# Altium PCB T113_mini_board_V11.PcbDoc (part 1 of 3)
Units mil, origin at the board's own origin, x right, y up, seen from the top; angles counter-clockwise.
Board outline 2716.54 x 2716.54 mil, 4 copper layers (Top Layer, GND, PWR, Bottom Layer); 97 components, 127 nets, 497 pads, 287 vias.
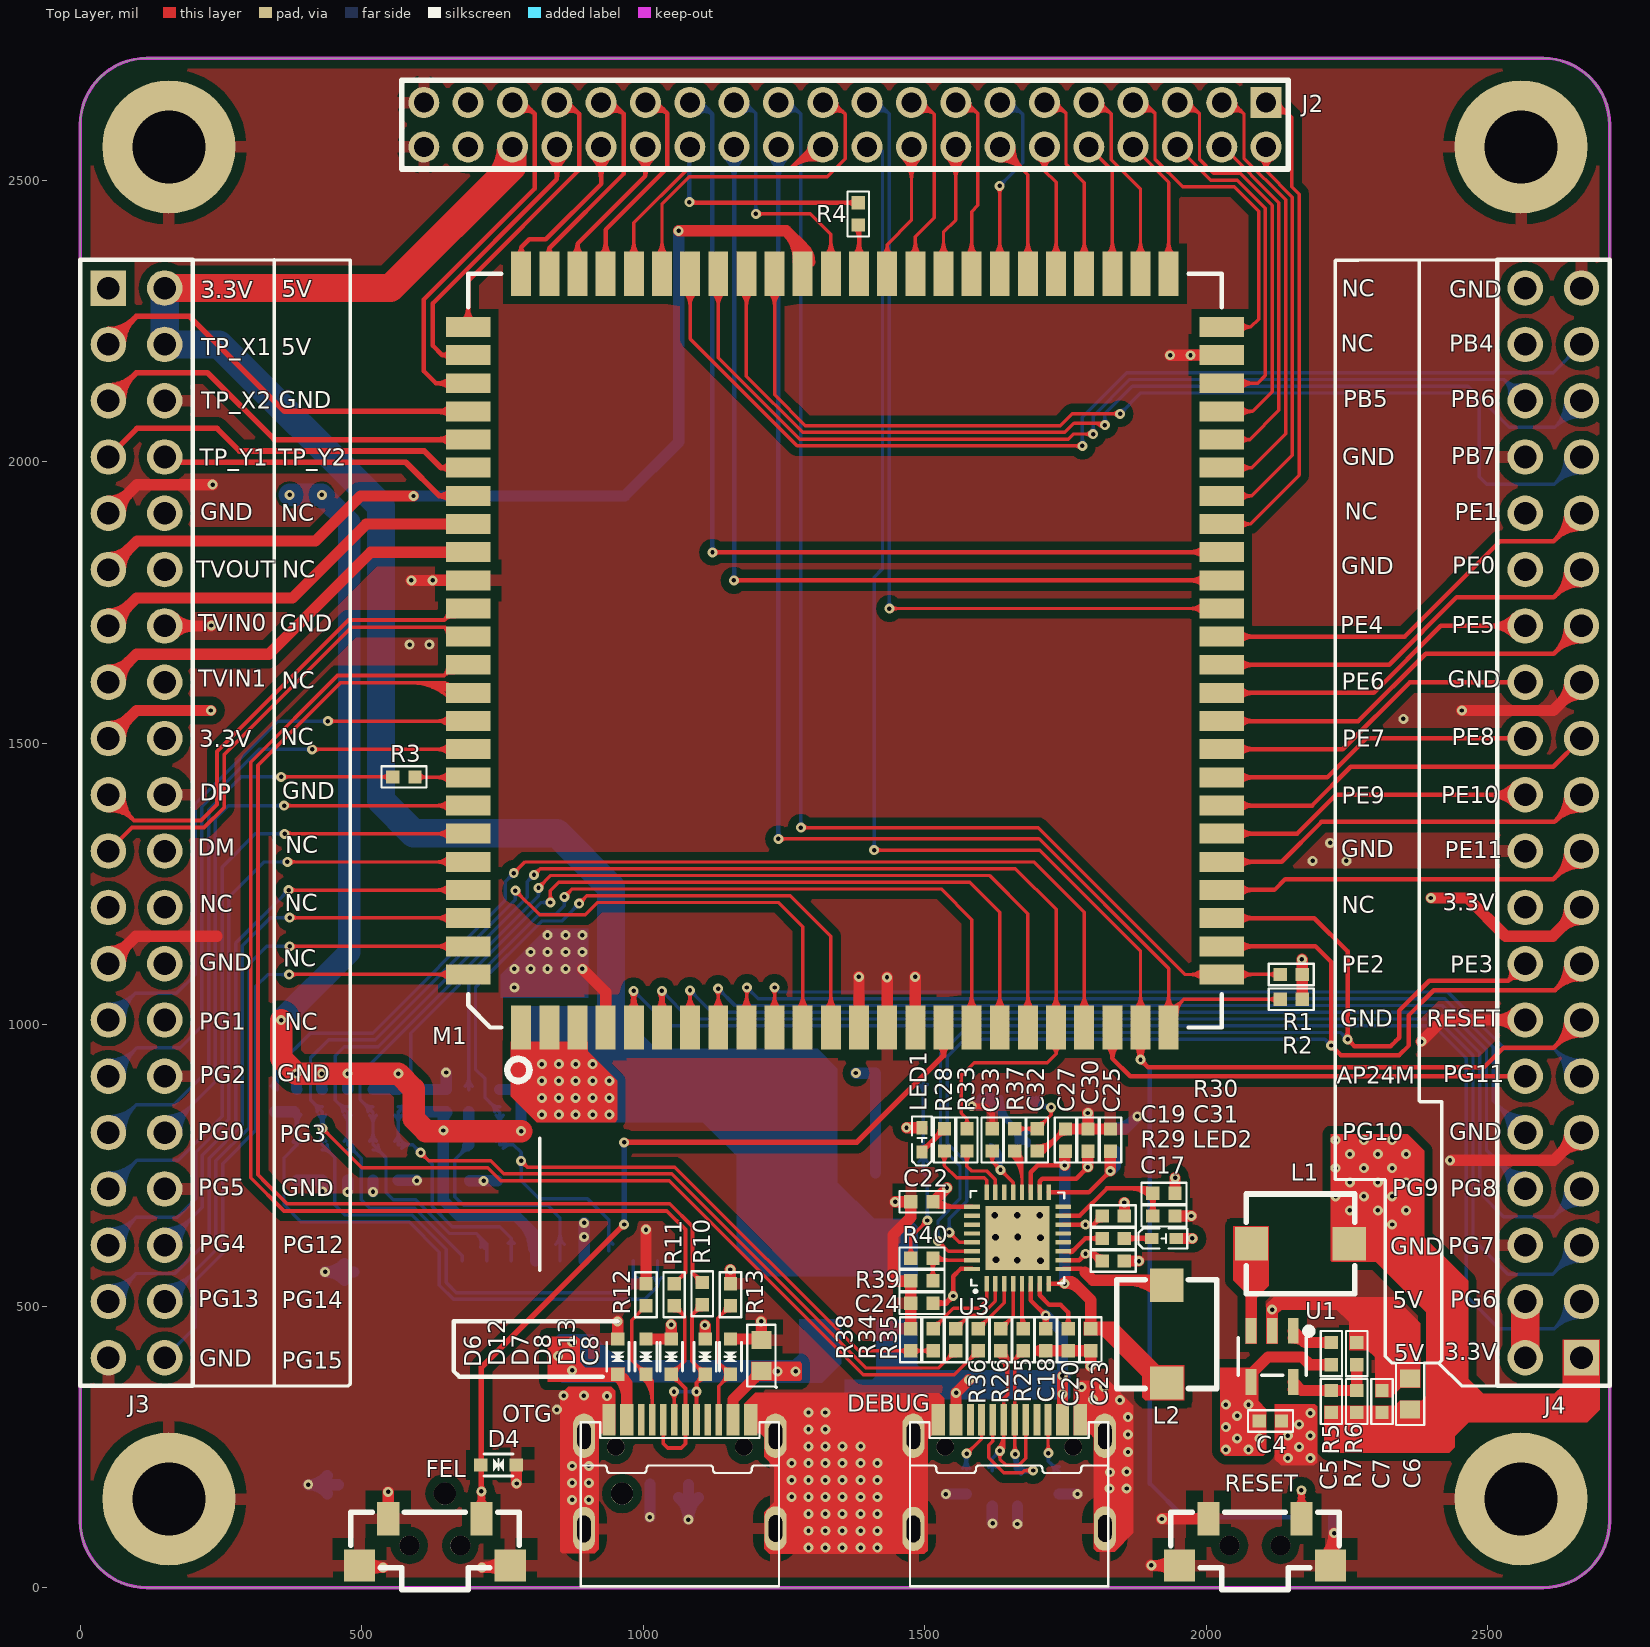
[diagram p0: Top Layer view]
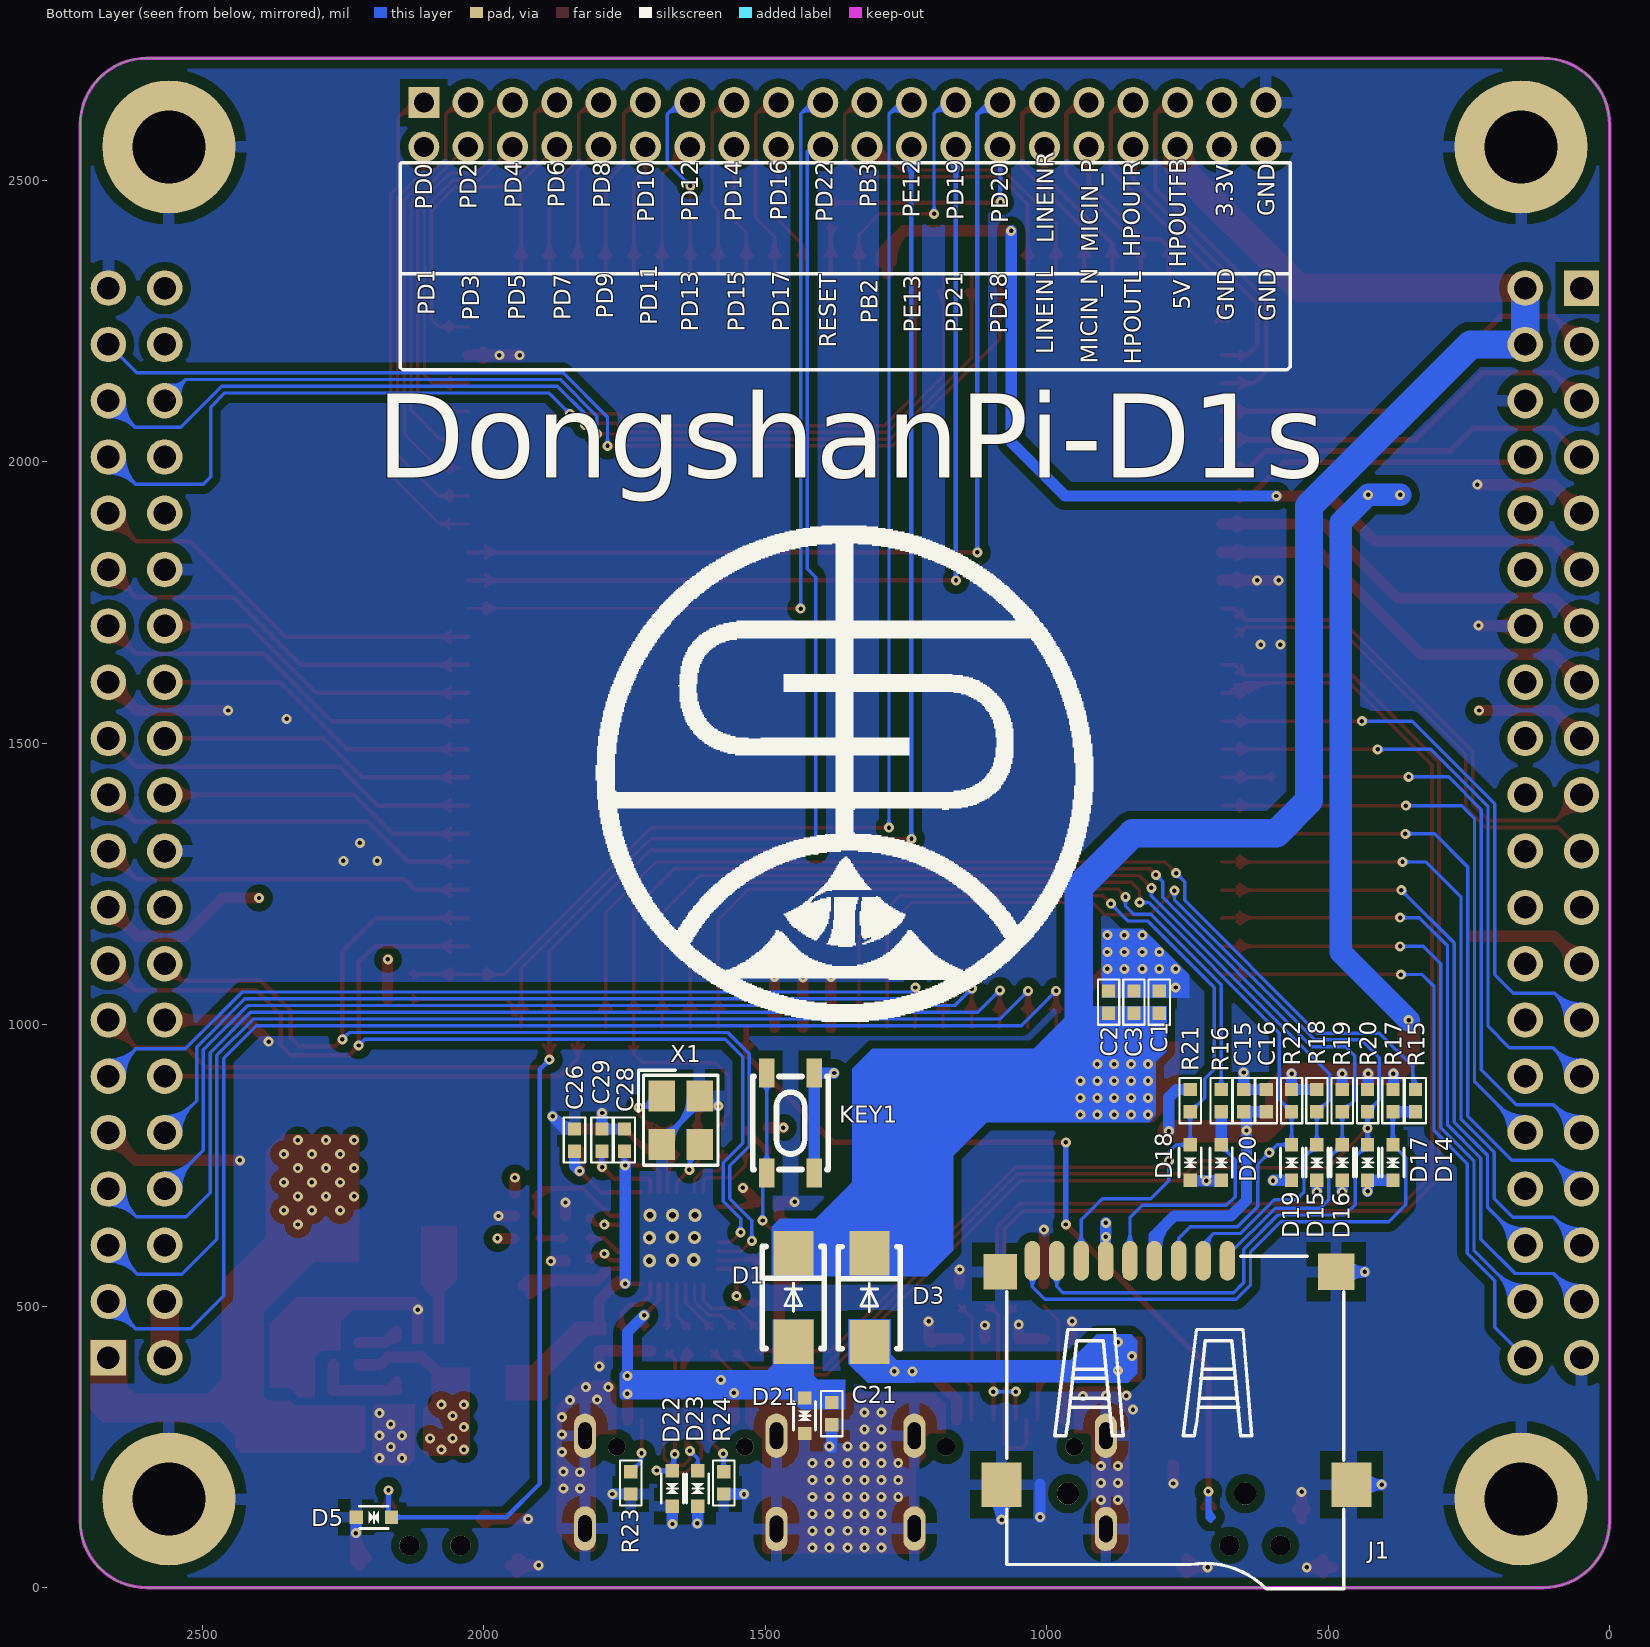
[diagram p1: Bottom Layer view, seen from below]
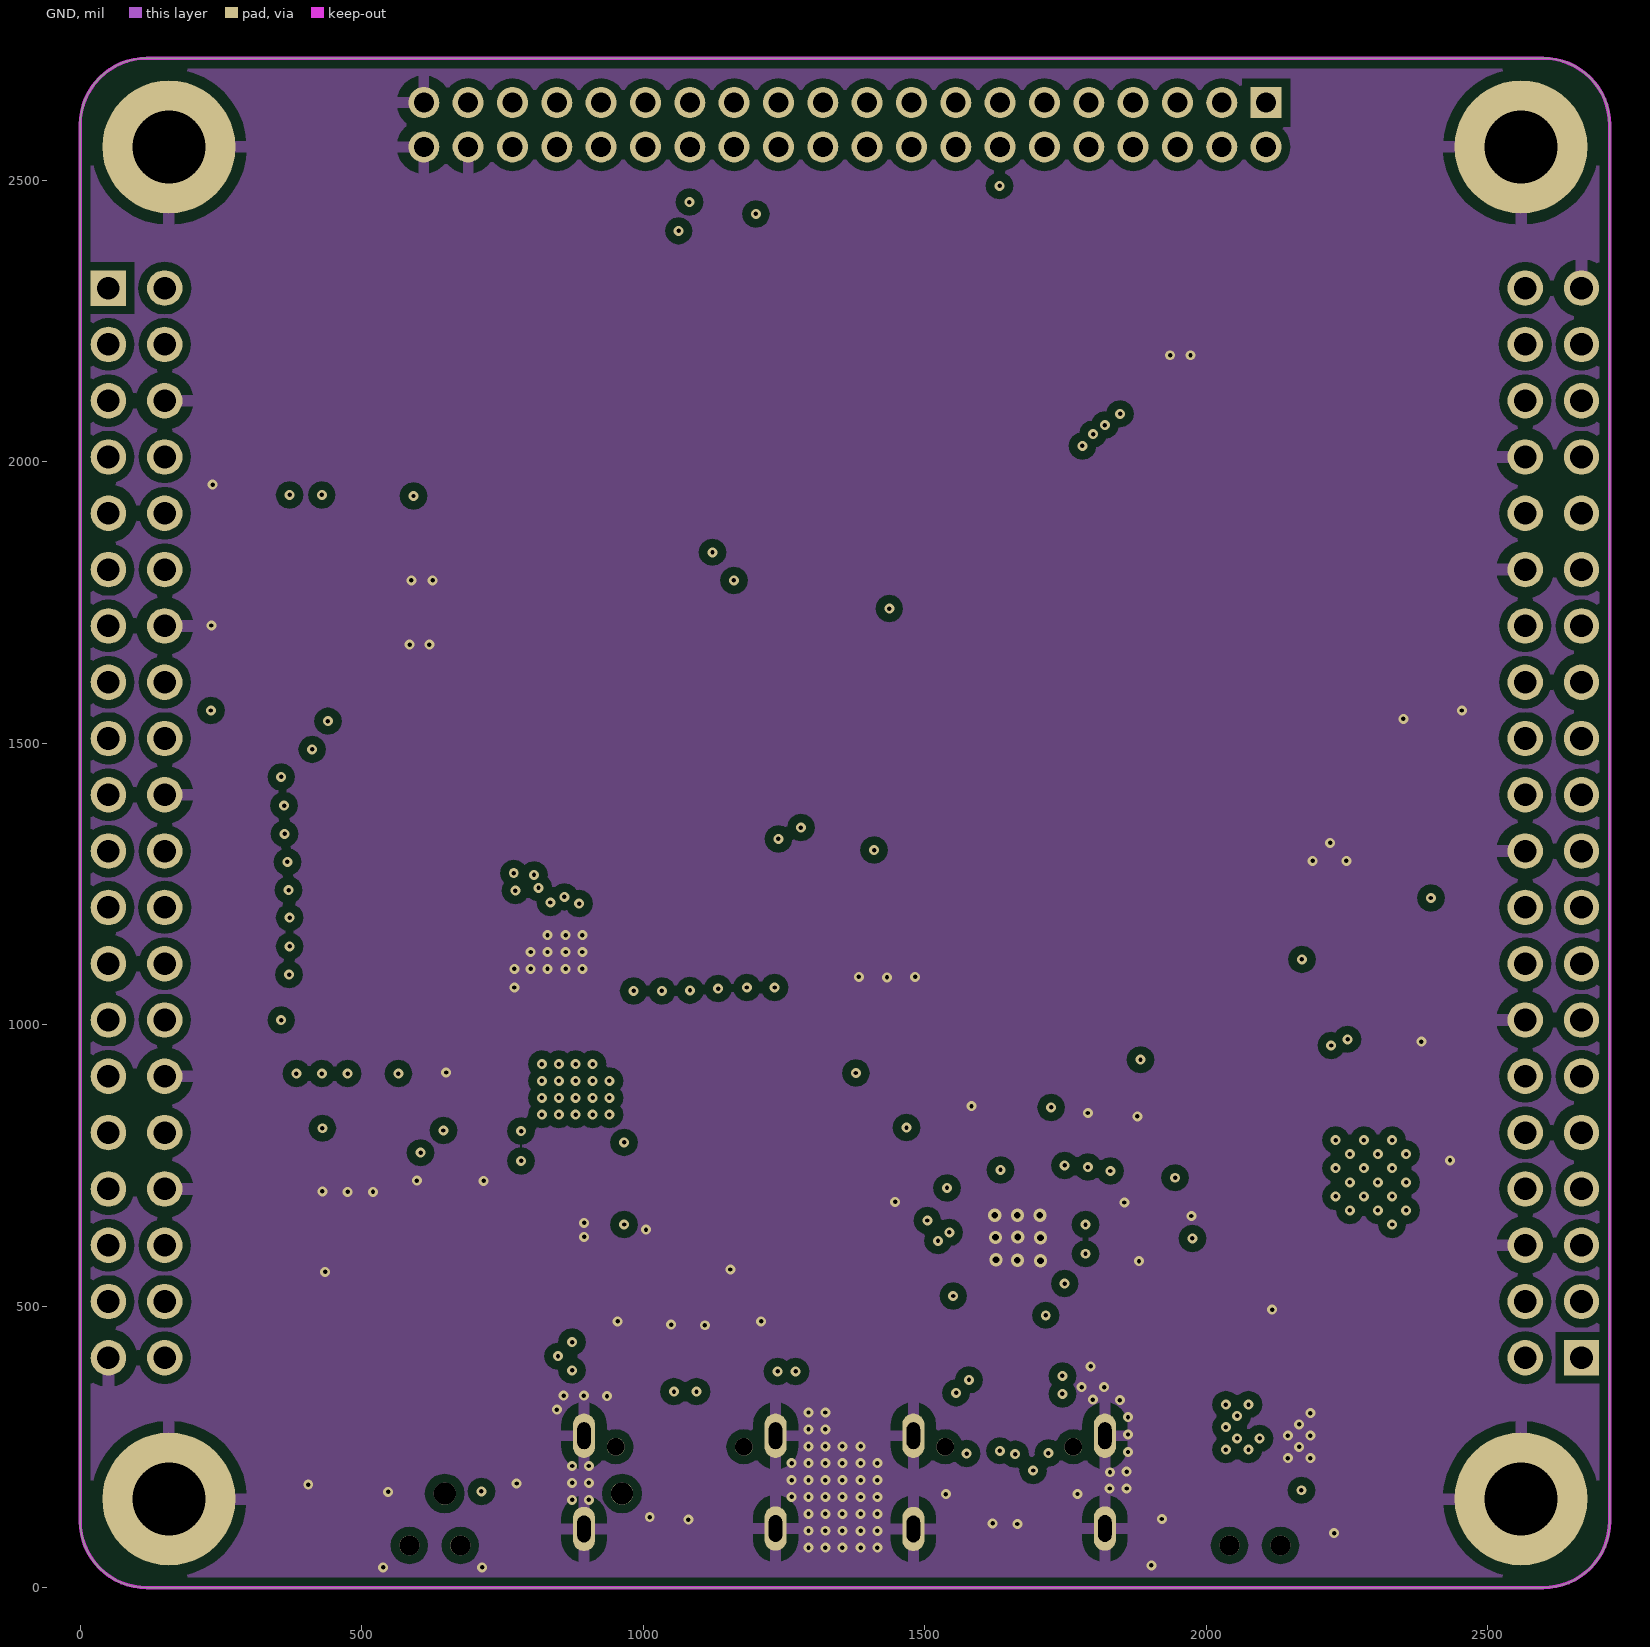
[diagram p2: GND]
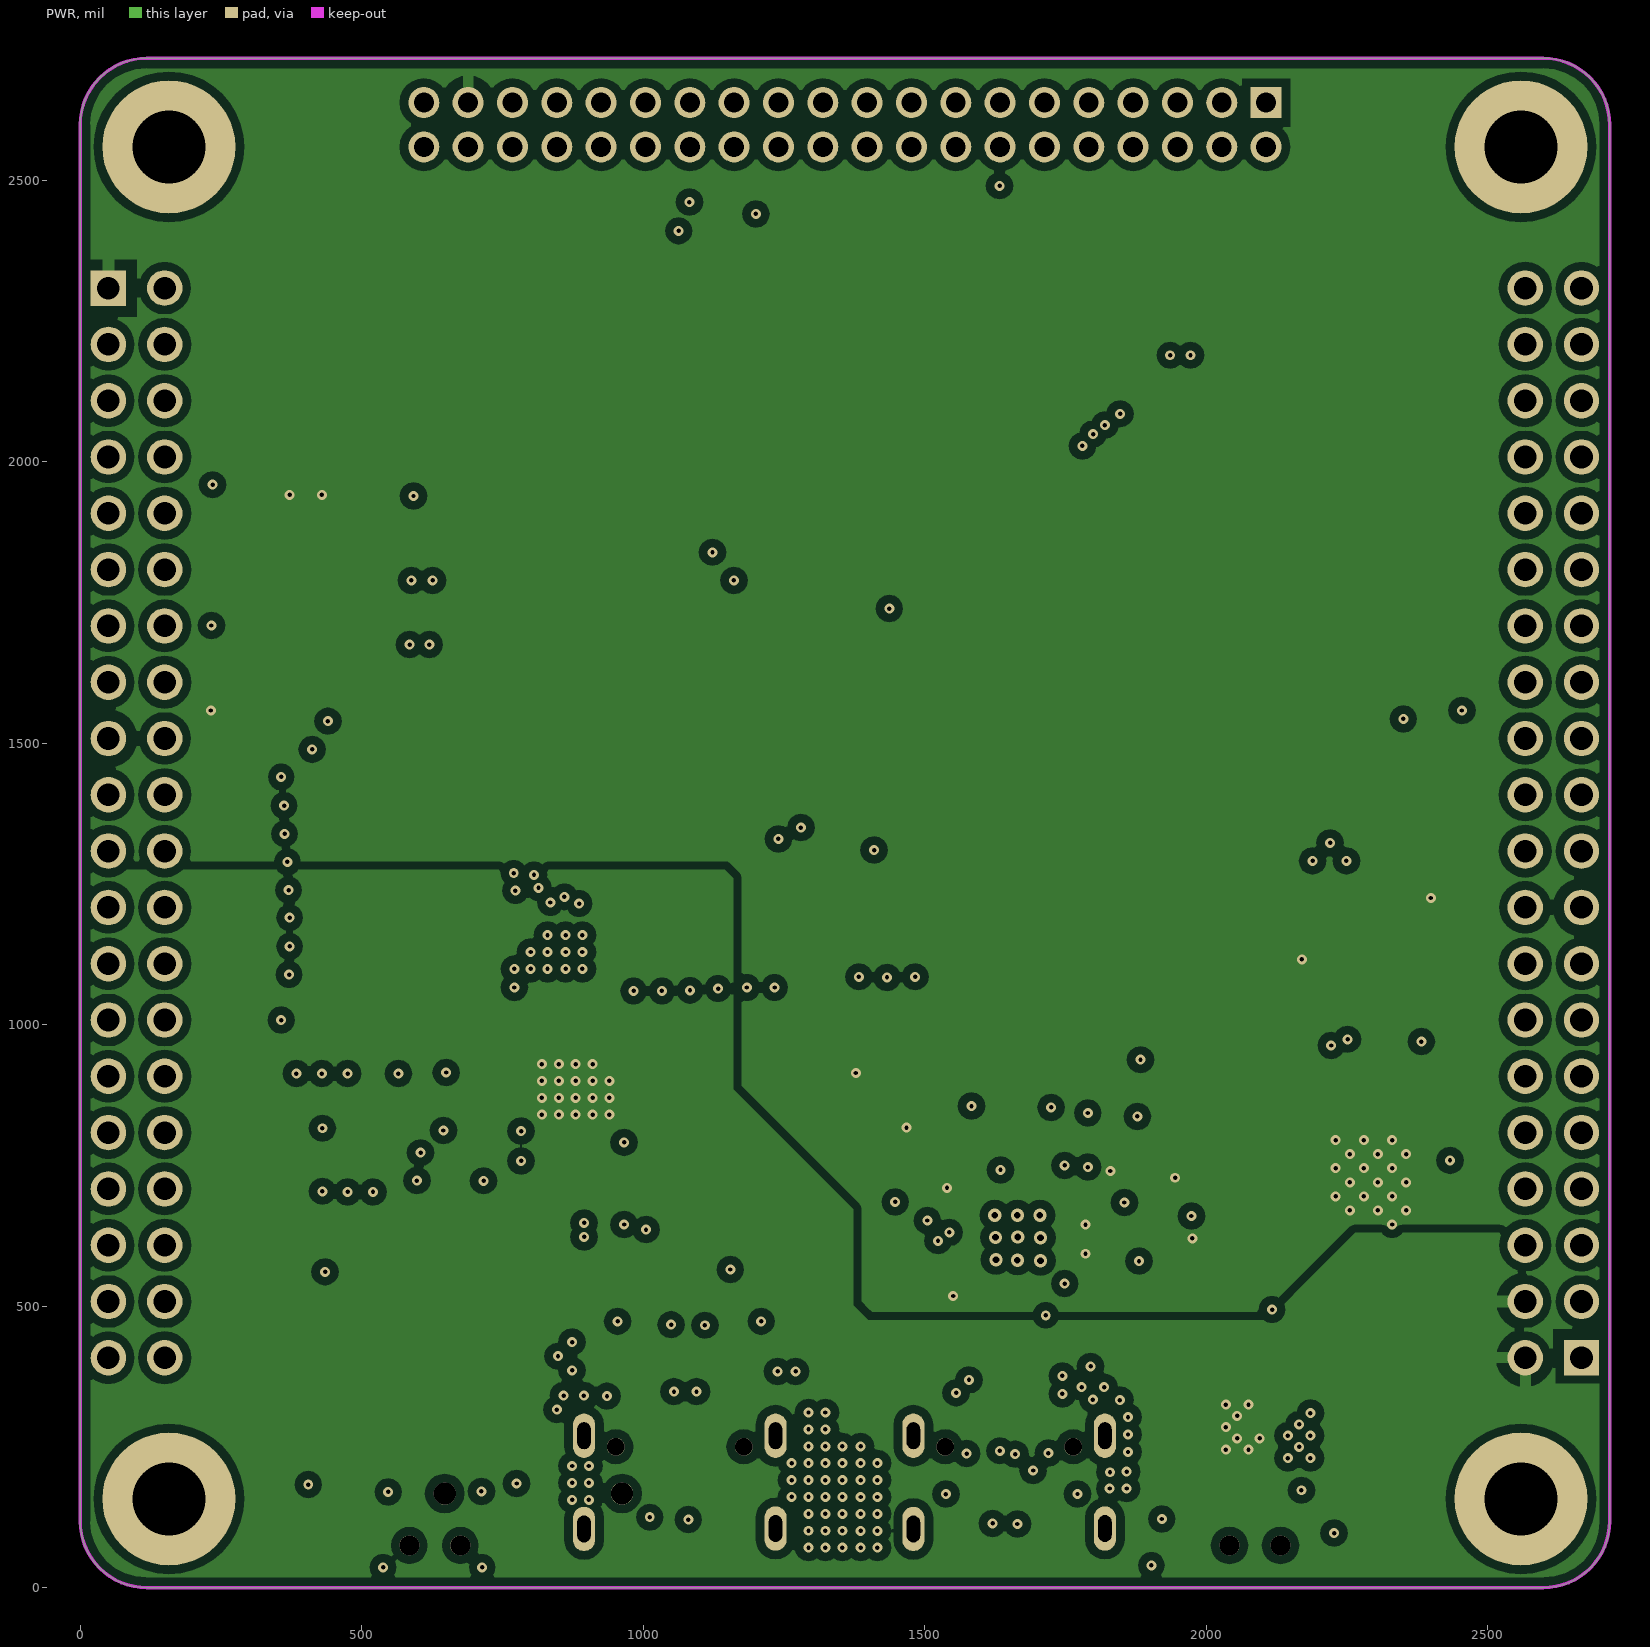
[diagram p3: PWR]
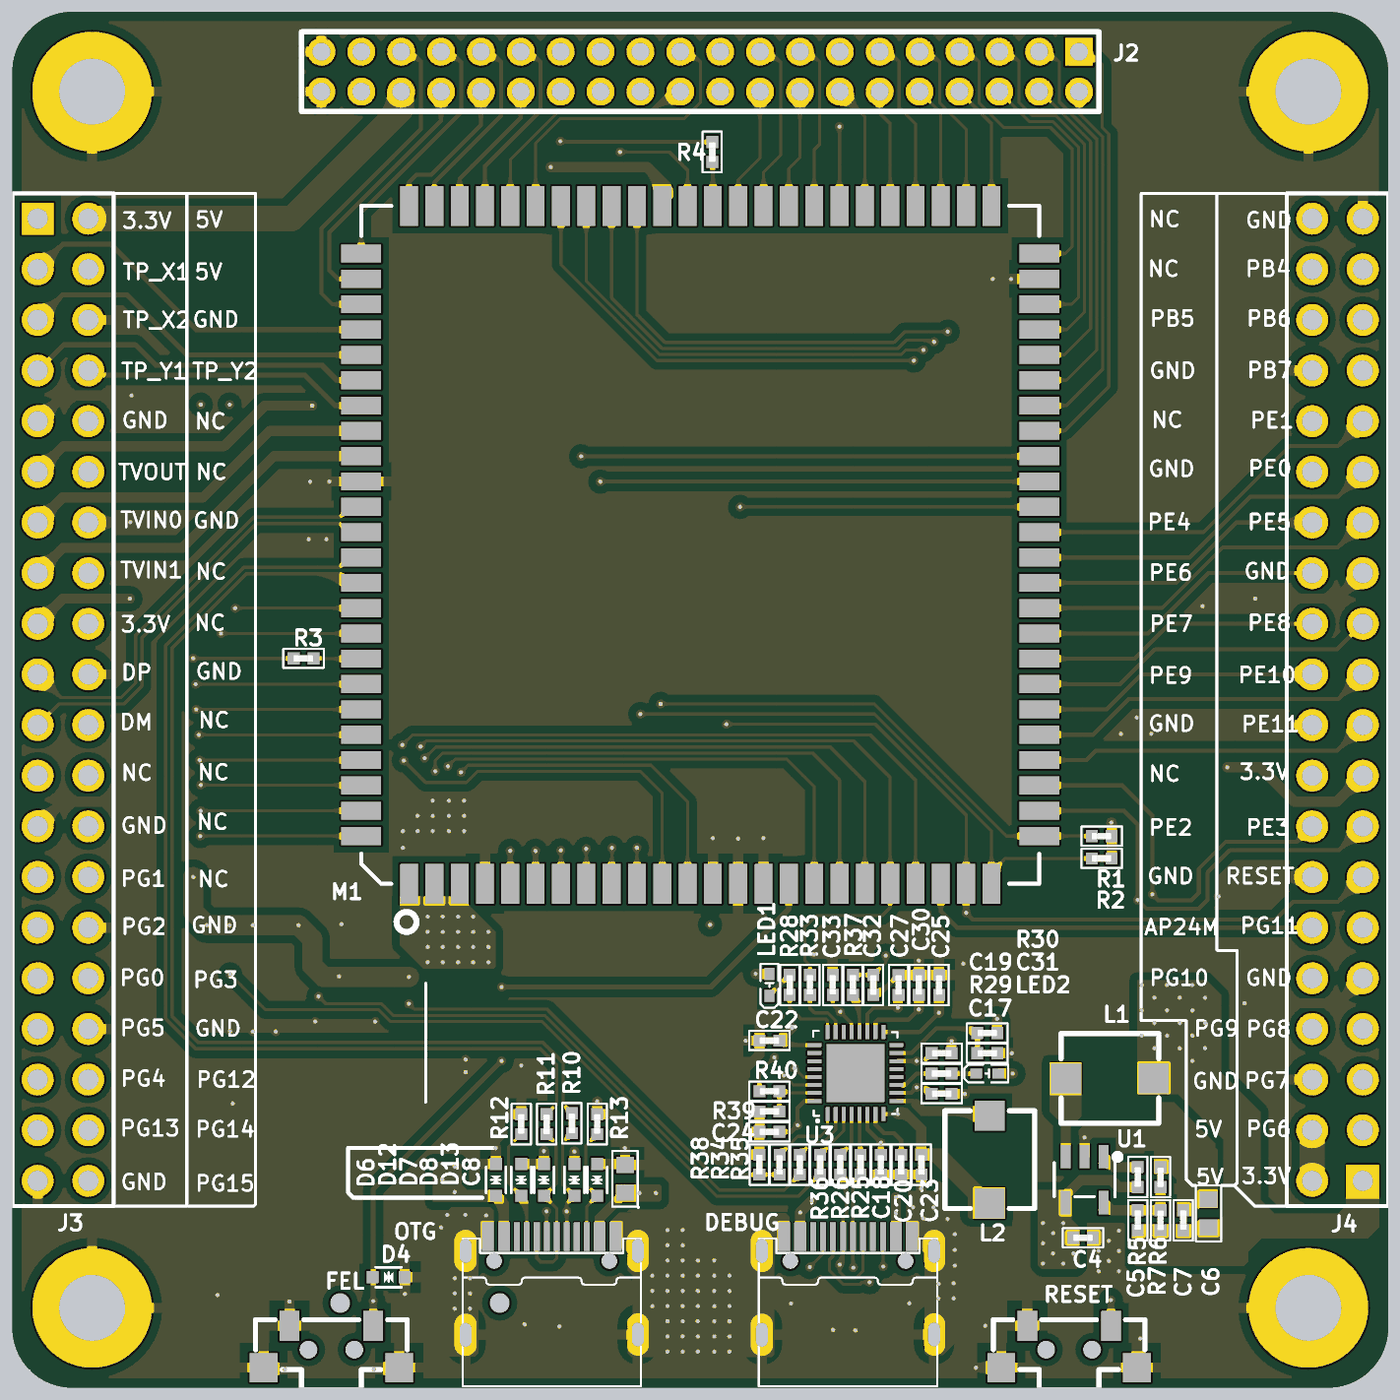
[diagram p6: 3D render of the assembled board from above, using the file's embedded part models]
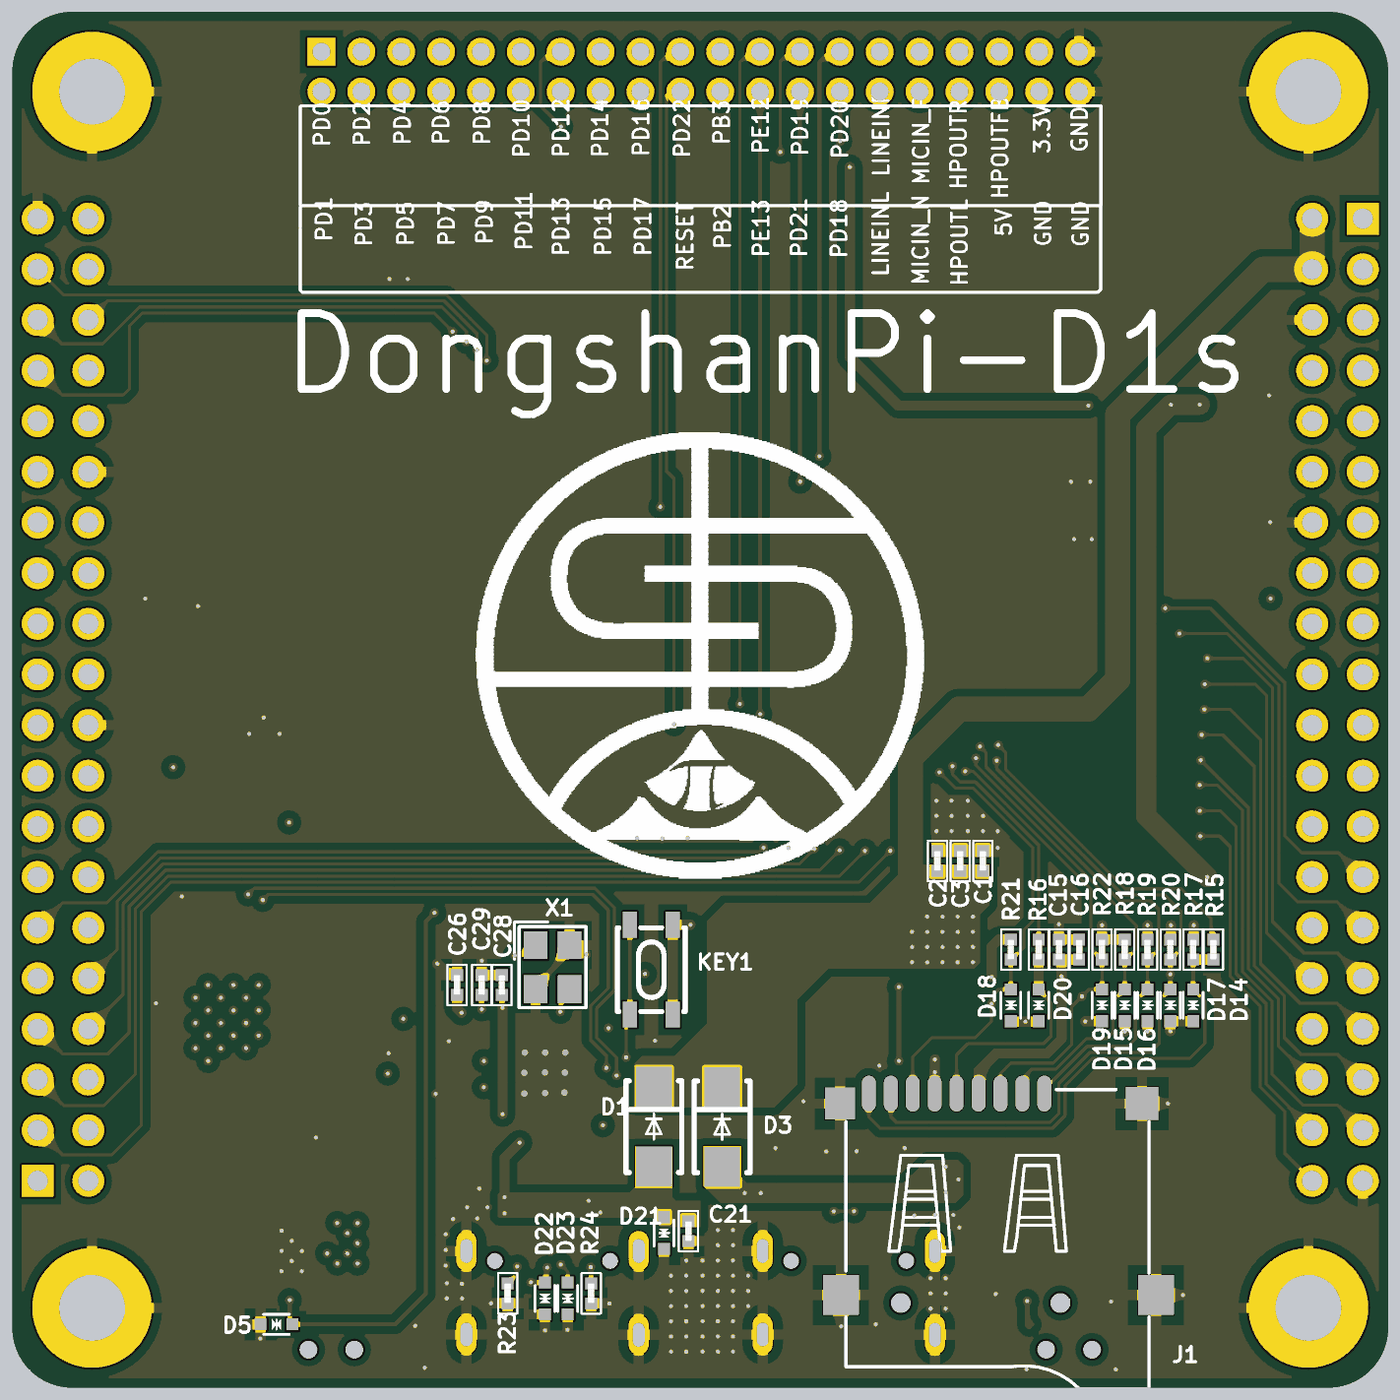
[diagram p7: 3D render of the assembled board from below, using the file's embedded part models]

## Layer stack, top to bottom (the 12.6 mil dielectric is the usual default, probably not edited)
Top Layer: signal copper 1.4
Dielectric: core 12.6, FR-4, Dk 4.8
GND: signal copper 1.4
Dielectric: prepreg 12.6, FR-4, Dk 4.8
PWR: signal copper 1.4
Dielectric: core 12.6, FR-4, Dk 4.8
Bottom Layer: signal copper 1.4

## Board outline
0,118.11 0,2598.43 cw(c118.11,2598.43) 118.11,2716.54 2598.43,2716.54 cw(c2598.43,2598.43) 2716.54,2598.43 2716.54,118.11 cw(c2598.43,118.11) 2598.43,0 118.11,0 cw(c118.11,118.11)

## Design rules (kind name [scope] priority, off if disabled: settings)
Clearance Clearance_1 [InPolygon] p1: gap=15
Clearance [All] p2: gap=6
ComponentClearance [All] p1 off: gap=10 collisioncheckmode=3 verticalgap=10 showdistances=FALSE
HoleSize [All] p1: absolutevalues=TRUE maxlimit=200 minlimit=1 maxpercent=80.000 minpercent=20.000
MinimumSolderMaskSliver [All] p1 off: minsoldermaskwidth=3
PolygonConnect PolygonConnect_1 [IsVia] p1: connectstyle=Direct reliefconductorwidth=10 reliefentries=4 polygonreliefangle="90 Angle" airgapwidth=10
PolygonConnect [All] p2: connectstyle=Relief reliefconductorwidth=20 reliefentries=4 polygonreliefangle="90 Angle" airgapwidth=20
RoutingLayers [All] p1: top layer_v5=TRUE mid layer 1_v5=FALSE mid layer 2_v5=FALSE bottom layer_v5=TRUE
RoutingVias [All] p1: holewidth=7.87 width=17.72 viastyle="Through Hole" minholewidth=7.87 minwidth=17.72 maxholewidth=7.87 maxwidth=17.72
SilkToSilkClearance [All] p1 off: silktosilkclearance=10
SilkToSolderMaskClearance [IsPad] p1 off: minsilkscreentomaskgap=3 clearancetoexposedcopper=TRUE
SolderMaskExpansion [All] p1: expansion=4
Width [All] p1: maxlimit=100 minlimit=4 preferedwidth=6 minimp=50.000000 maximp=50.000000 favimp=50.000000
22 further rules are at their usual default settings.

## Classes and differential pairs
component class INTERFACE: J2 J3 J4
component class USB_OTG&DEBUG&TF: C8 C15 C16 D6 D7 D8 D12 D13 D14 D15 D16 D17 D18 D19 D20 J1 OTG R10 R11 R12 R13 R15 R16 R17 R18 R19 R20 R21 R22
component class F133_CORE_INTERFACE: C1 C2 C3 C4 C5 C6 C7 D1 D3 D4 D5 FEL L1 M1 R1 R2 R3 R4 R5 R6 R7 RESET U1
component class BL702: C17 C18 C19 C20 C21 C22 C23 C24 C25 C26 C27 C28 C29 C30 C31 C32 C33 D21 D22 D23 DEBUG KEY1 L2 LED1 LED2 R23 R24 R25 R26 R28 R29 R30 R33 R34 R35 R36 R37 R38 R39 R40 U3 X1

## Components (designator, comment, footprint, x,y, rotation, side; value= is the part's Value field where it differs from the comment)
C1 "10uF" 0402 800,1040 r270 bottom
C2 "10uF" 0402 890,1040 r270 bottom
C3 "0.1uF" 0402 845,1040 r270 bottom
C4 "4.7uF/10V" 0402 2114,296 r180 top
C5 "22pF_NC" 0402 2222.21,330.66 r270 top
C6 "22uF/10V" 0603 2362,344 r270 top
C7 "0.1uF" 0402 2312.21,330.66 r270 top
C8 "22uF/10V" 0603 1209.88,412.18 r270 top
C15 "10uF/10V" 0402 650,865 r90 bottom
C16 "0.1uF" 0402 610,865 r90 bottom
C17 "2.2uF/10V" 0402 1834.92,580.3 r180 top
C18 "2.2uF/10V" 0402 1714.92,440.3 r90 top
C19 "2.2uF/10V" 0402 1834.92,660.3 r180 top
C20 "2.2uF/10V" 0402 1754.92,440.3 r90 top
C21 "10uF/10V" 0402 1381.58,309.09 r90 bottom
C22 "2.2uF/10V" 0402 1494.92,685.3 r0 top
C23 "2.2uF/10V" 0402 1794.92,440.3 r90 top
C24 "2.2uF/10V" 0402 1494.92,505.3 r0 top
C25 "10pF" 0402 1829.92,794.99 r270 top
C26 "10uF/10V" 0402 1838.58,795.09 r270 bottom
C27 "10pF" 0402 1749.92,794.99 r270 top
C28 "0.1uF" 0402 1749.92,794.99 r270 bottom
C29 "2.2uF/10V" 0402 1789.92,794.99 r270 bottom
C30 "10pF" 0402 1789.92,794.99 r270 top
C31 "0.1uF" 0402 1924.92,660.3 r180 top
C32 "10pF" 0402 1699.92,795.3 r90 top
C33 "10pF" 0402 1619.92,795.3 r270 top
D1 "SS34" SMA 1449.92,515.3 r270 bottom
D3 "SS34" SMA 1315,515 r270 bottom
D4 "LESD5D5.0CT1G" SOD-523_L1.2-W0.8-LS1.6-BI 743,218 r180 top
D5 "LESD5D5.0CT1G" SOD-523_L1.2-W0.8-LS1.6-BI 2195,125 r180 bottom
D6 "LESD5D5.0CT1G" SOD-523_L1.2-W0.8-LS1.6-BI 954.92,410.3 r270 top
D7 "LESD5D5.0CT1G" SOD-523_L1.2-W0.8-LS1.6-BI 1049.92,410.3 r270 top
D8 "LESD5D5.0CT1G" SOD-523_L1.2-W0.8-LS1.6-BI 1109.92,410.3 r270 top
D12 "LESD5D5.0CT1G" SOD-523_L1.2-W0.8-LS1.6-BI 1004.92,410.3 r270 top
D13 "LESD5D5.0CT1G" SOD-523_L1.2-W0.8-LS1.6-BI 1154.92,410.3 r270 top
D14 "LESD5D5.0CT1G" SOD-523_L1.2-W0.8-LS1.6-BI 385,755 r90 bottom
D15 "LESD5D5.0CT1G" SOD-523_L1.2-W0.8-LS1.6-BI 520,755 r90 bottom
D16 "LESD5D5.0CT1G" SOD-523_L1.2-W0.8-LS1.6-BI 475,755 r90 bottom
D17 "LESD5D5.0CT1G" SOD-523_L1.2-W0.8-LS1.6-BI 430,755 r90 bottom
D18 "LESD5D5.0CT1G" SOD-523_L1.2-W0.8-LS1.6-BI 745,755 r90 bottom
D19 "LESD5D5.0CT1G" SOD-523_L1.2-W0.8-LS1.6-BI 565,755 r90 bottom
D20 "LESD5D5.0CT1G" SOD-523_L1.2-W0.8-LS1.6-BI 690,755 r90 bottom
D21 "LESD5D5.0CT1G" SOD-523_L1.2-W0.8-LS1.6-BI 1429.92,305.3 r90 bottom
D22 "LESD5D5.0CT1G" SOD-523_L1.2-W0.8-LS1.6-BI 1664.92,176.09 r90 bottom
D23 "LESD5D5.0CT1G" SOD-523_L1.2-W0.8-LS1.6-BI 1619.92,176.09 r90 bottom
DEBUG "U262-16XN-4BVC11" "TYPEC-12PIN - duplicate" 1649.92,105.3 r0 top
FEL "1TS002G-1300-3500" SW-SMD_1TS002G-XXXX-3500-CT 629.92,68.82 r0 top
J1 "SD_MR01A_01211" SD-MR01A-01211 771.34,289.21 r180 bottom
J2 "2*20P,2毫米间距双排插针" HDR-TH_40P-P2.00-V-M-R2-C20-S2.00 1358.27,2598.43 r180 top
J3 "RASPBERRY_PI_40P" IDE2X20 100,1358.27 r270 top
J4 "RASPBERRY_PI_40P" IDE2X20 2616.54,1358.27 r90 top
KEY1 "TS-KG89S-AT25F" SW-SMD_4P-L4.2-W3.3-P2.15-LS5.1 1454.92,825.3 r90 bottom
L1 "JSHC0420-2R2M" IND-SMD_L4.9-W4.5 2167.21,610.66 r0 top
L2 "JSHC0420-2R2M" IND-SMD_L4.9-W4.5 1929.92,450.3 r90 top
LED1 "GreenLED" LED0402 1494.92,795.3 r90 top
LED2 "GreenLED" LED0402 1924.92,620.3 r0 top
M1 "F133-CORE-CARD" F133_CORE_V10 1358.27,1664.21 r90 top
OTG "U262-16XN-4BVC11" "TYPEC-12PIN - duplicate" 1064.92,105.3 r0 top
R1 "10K" 0402 2151,1089 r0 top
R2 "10K" 0402 2151,1045 r0 top
R3 "33R" 0402 575,1440 r0 top
R4 "33R" 0402 1382,2440 r90 top
R5 "100K" 0402 2222.21,415.66 r270 top
R6 "100K" 0402 2267.21,415.66 r90 top
R7 "453K" 0402 2267.21,330.66 r90 top
R10 "22R" 0402 1104.88,522.18 r90 top
R11 "22R" 0402 1054.92,520.3 r90 top
R12 "10K" 0402 1004.92,520.3 r270 top
R13 "10K" 0402 1154.92,520.3 r270 top
R15 "22R" 0402 345,865 r90 bottom
R16 "33R" 0402 690,865 r90 bottom
R17 "10K" 0402 385,865 r270 bottom
R18 "47K" 0402 520,865 r270 bottom
R19 "47K" 0402 475,865 r270 bottom
R20 "47K" 0402 430,865 r270 bottom
R21 "47K" 0402 745,865 r270 bottom
R22 "10K" 0402 565,865 r270 bottom
R23 "5.1K" 0402 1738.58,186.09 r270 bottom
R24 "5.1K" 0402 1573.58,186.09 r270 bottom
R25 "22R" 0402 1674.92,440.3 r270 top
R26 "22R" 0402 1634.92,440.3 r270 top
R28 "510R" 0402 1534.92,795.3 r90 top
R29 "510R" 0402 1834.92,620.3 r0 top
R30 "100K" 0402 1924.92,700.3 r180 top
R33 "22R" 0402 1574.92,795.3 r270 top
R34 "22R" 0402 1514.92,440.3 r90 top
R35 "22R" 0402 1554.92,440.3 r90 top
R36 "22R" 0402 1594.92,440.3 r90 top
R37 "22R" 0402 1659.92,795.3 r270 top
R38 "680K" 0402 1474.92,440.3 r270 top
R39 "33K" 0402 1494.92,545.3 r180 top
R40 "510R" 0402 1494.92,585.3 r180 top
RESET "1TS002G-1300-3500" SW-SMD_1TS002G-XXXX-3500-CT 2086.61,68.81 r0 top
U1 "SY8089A1AAC" SOT-23-5_L3.0-W1.7-P0.95-LS2.8-BL 2117.21,410.66 r180 top
U3 "BL702S-A0-Q2I" QFN-32_L4.0-W4.0-P0.40-TL-EP2.9 1664.92,620.3 r90 top
X1 "32MHz" OSC-SMD_4P-L3.2-W2.5-BL 1649.92,830.3 r270 bottom

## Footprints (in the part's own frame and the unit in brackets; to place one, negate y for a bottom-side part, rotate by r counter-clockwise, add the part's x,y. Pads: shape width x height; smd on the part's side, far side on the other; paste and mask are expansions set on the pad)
0402 [mm]
  rect 0.6x0.6 smd: 1(-0.5,0) 2(0.5,0)
  silkscreen extent -1.02,-0.48 1.02,0.48, body extent -0.51,-0.18 0.49,0.18, height 0.27
0603 [mm] "Chip Capacitor, Body 1.6x0.8mm, IPC High Density"
  rect 0.8x0.9 smd: 1(-0.7,0) 2(0.7,0)
  silkscreen extent -1.4,-0.64 1.4,0.64, body extent -0.87,-0.48 0.87,0.48, height 1.3
F133_CORE_V10 [mm]
  rect 2x0.9 smd: 1(-17,14.605) 2(-17,13.335) 3(-17,12.065) 4(-17,10.795) 5(-17,9.525) 6(-17,8.255) 7(-17,6.985) 8(-17,5.715) 9(-17,4.445) 10(-17,3.175) 11(-17,1.905) 12(-17,0.635) 13(-17,-0.635) 14(-17,-1.905) 15(-17,-3.175) 16(-17,-4.445) 17(-17,-5.715) 18(-17,-6.985) 19(-17,-8.255) 20(-17,-9.525) 21(-17,-10.795) 22(-17,-12.065) 23(-17,-13.335) 24(-17,-14.605) 49(17,-14.605) 50(17,-13.335) 51(17,-12.065) 52(17,-10.795) 53(17,-9.525) 54(17,-8.255) 55(17,-6.985) 56(17,-5.715) 57(17,-4.445) 58(17,-3.175) 59(17,-1.905) 60(17,-0.635) 61(17,0.635) 62(17,1.905) 63(17,3.175) 64(17,4.445) 65(17,5.715) 66(17,6.985) 67(17,8.255) 68(17,9.525) 69(17,10.795) 70(17,12.065) 71(17,13.335) 72(17,14.605)
  rect 0.9x2 smd: 25(-14.605,-17) 26(-13.335,-17) 27(-12.065,-17) 28(-10.795,-17) 29(-9.525,-17) 30(-8.255,-17) 31(-6.985,-17) 32(-5.715,-17) 33(-4.445,-17) 34(-3.175,-17) 35(-1.905,-17) 36(-0.635,-17) 37(0.635,-17) 38(1.905,-17) 39(3.175,-17) 40(4.445,-17) 41(5.715,-17) 42(6.985,-17) 43(8.255,-17) 44(9.525,-17) 45(10.795,-17) 46(12.065,-17) 47(13.335,-17) 48(14.605,-17) 73(14.605,17) 74(13.335,17) 75(12.065,17) 76(10.795,17) 77(9.525,17) 78(8.255,17) 79(6.985,17) 80(5.715,17) 81(4.445,17) 82(3.175,17) 83(1.905,17) 84(0.635,17) 85(-0.635,17) 86(-1.905,17) 87(-3.175,17) 88(-4.445,17) 89(-5.715,17) 90(-6.985,17) 91(-8.255,17) 92(-9.525,17) 93(-10.795,17) 94(-12.065,17) 95(-13.335,17) 96(-14.605,17)
  silkscreen extent -19.41,-17 17,17
HDR-TH_40P-P2.00-V-M-R2-C20-S2.00 [mm]
  rect 1.4x1.4 hole 0.9: 1(-19,-1)
  round 1.4 hole 0.9: 2(-19,1) 3(-17,-1) 4(-17,1) 5(-15,-1) 6(-15,1) 7(-13,-1) 8(-13,1) 9(-11,-1) 10(-11,1) 11(-9,-1) 12(-9,1) 13(-7,-1) 14(-7,1) 15(-5,-1) 16(-5,1) 17(-3,-1) 18(-3,1) 19(-1,-1) 20(-1,1) 21(1,-1) 22(1,1) 23(3,-1) 24(3,1) 25(5,-1) 26(5,1) 27(7,-1) 28(7,1) 29(9,-1) 30(9,1) 31(11,-1) 32(11,1) 33(13,-1) 34(13,1) 35(15,-1) 36(15,1) 37(17,-1) 38(17,1) 39(19,-1) 40(19,1)
  silkscreen extent -20,-2 20,2
IDE2X20 [mm]
  rect 1.6x1.6 hole 1.02: 1(-24.13,-1.27)
  round 1.6 hole 1.02: 2(-24.13,1.27) 3(-21.59,-1.27) 4(-21.59,1.27) 5(-19.05,-1.27) 6(-19.05,1.27) 7(-16.51,-1.27) 8(-16.51,1.27) 9(-13.97,-1.27) 10(-13.97,1.27) 11(-11.43,-1.27) 12(-11.43,1.27) 13(-8.89,-1.27) 14(-8.89,1.27) 15(-6.35,-1.27) 16(-6.35,1.27) 17(-3.81,-1.27) 18(-3.81,1.27) 19(-1.27,-1.27) 20(-1.27,1.27) 21(1.27,-1.27) 22(1.27,1.27) 23(3.81,-1.27) 24(3.81,1.27) 25(6.35,-1.27) 26(6.35,1.27) 27(8.89,-1.27) 28(8.89,1.27) 29(11.43,-1.27) 30(11.43,1.27) 31(13.97,-1.27) 32(13.97,1.27) 33(16.51,-1.27) 34(16.51,1.27) 35(19.05,-1.27) 36(19.05,1.27) 37(21.59,-1.27) 38(21.59,1.27) 39(24.13,-1.27) 40(24.13,1.27)
  silkscreen extent -25.4,-2.54 25.4,2.54
IND-SMD_L4.9-W4.5 [mm]
  rect 1.5x1.5 smd: 1(-2.2,0) 2(2.2,0)
  silkscreen extent -2.45,-2.25 2.45,2.25
LED0402 [mm]
  rect 0.6x0.5 smd: 1(0.55,0) 2(-0.55,0)
  silkscreen extent -1.15,-0.45 1.05,0.45
OSC-SMD_4P-L3.2-W2.5-BL [mm]
  rect 1.4x1.2 smd: 1(-1.1,-0.85) 2(1.1,-0.85) 3(1.1,0.85) 4(-1.1,0.85)
  silkscreen extent -2.26,-1.91 2.03,1.68
QFN-32_L4.0-W4.0-P0.40-TL-EP2.9 [mm]
  rect 0.7x0.2 smd: 1(-2.035,1.4) 2(-2.035,1) 3(-2.035,0.6) 4(-2.035,0.2) 5(-2.035,-0.2) 6(-2.035,-0.6) 7(-2.035,-1) 8(-2.035,-1.4) 17(2.078,-1.4) 18(2.078,-1) 19(2.078,-0.6) 20(2.078,-0.2) 21(2.078,0.2) 22(2.078,0.6) 23(2.078,1) 24(2.078,1.4)
  rect 0.2x0.7 smd: 9(-1.378,-2.057) 10(-0.978,-2.057) 11(-0.578,-2.057) 12(-0.178,-2.057) 13(0.221,-2.057) 14(0.622,-2.057) 15(1.022,-2.057) 16(1.422,-2.057) 25(1.422,2.057) 26(1.022,2.057) 27(0.622,2.057) 28(0.221,2.057) 29(-0.178,2.057) 30(-0.578,2.057) 31(-0.978,2.057) 32(-1.378,2.057)
  rect 2.9x2.9 smd: 33(0.022,0)
  silkscreen extent -2.38,-2.1 2.14,2.12
SD-MR01A-01211 [mm]
  oval 0.7x1.8 smd mask+0.05: 1(2.35,7.4) 2(1.25,7.4) 3(0.15,7.4) 4(-0.95,7.4) 5(-2.05,7.4) 6(-3.15,7.4) 7(-4.25,7.4) 8(-5.35,7.4) 9(-6.45,7.4)
  rect 1.5x1.6 smd mask+0.05: 10(-7.9,6.9)
  rect 1.65x1.65 smd mask+0.05: 11(7.25,6.9)
  rect 1.8x2 smd mask+0.05: 12(-7.85,-2.7) 13(7.95,-2.7)
  round 1 hole 1 unplated: 14(3.15,-3.1) 15(-4.85,-3.1)
  silkscreen extent -7.6,-7.4 7.6,7.6
SMA [mm]
  rect 2x1.8 smd: 1(2,0) 2(-2,0)
  silkscreen extent -2.3,-1.4 2.3,1.4
SOD-523_L1.2-W0.8-LS1.6-BI [mm]
  rect 0.6x0.6 smd: 1(-0.8,0) 2(0.8,0)
  silkscreen extent -0.65,-0.5 0.65,0.5
SOT-23-5_L3.0-W1.7-P0.95-LS2.8-BL [mm]
  rect 0.49x1.157 smd: 1(-0.95,-1.154) 2(0,-1.154) 3(0.95,-1.154)
  rect 0.49x1.175 smd: 4(0.95,1.154) 5(-0.95,1.154)
  silkscreen extent -1.8,-1.29 1.53,0.85
SW-SMD_1TS002G-XXXX-3500-CT [mm]
  rect 1x1.5 smd: 1(-2.1,1.357) 2(2.1,1.357)
  rect 1.4x1.45 smd: 3(-3.4,-0.743) 4(3.4,-0.743)
  round 0.9 hole 0.9 unplated: ""(-1.15,0.157) ""(1.15,0.157)
  silkscreen extent -3.8,-1.84 3.8,1.66
SW-SMD_4P-L4.2-W3.3-P2.15-LS5.1 [mm]
  rect 1.3x0.7 smd: 1(-2.25,1.075) 2(2.25,1.075) 3(-2.25,-1.075) 4(2.25,-1.075)
  silkscreen extent -2.1,-1.7 2.1,1.7
"TYPEC-12PIN - duplicate" [mm]
  rect 0.6x1.44 smd mask+0.06: A1B12(-3.195,4.9) A4B9(-2.395,4.9) B1A12(3.205,4.9) B4A9(2.405,4.9)
  rect 0.3x1.44 smd mask+0.06: A5(-1.245,4.9) A6(-0.245,4.9) A7(0.255,4.9) A8(1.255,4.9) B5(1.755,4.9) B6(0.755,4.9) B7(-0.745,4.9) B8(-1.745,4.9)
  oval 1x2 hole 0.6 slot 1.2 at 90 deg mask+0.06: SHELL(-4.32,-0.025) SHELL(-4.32,4.18) SHELL(4.32,-0.008) SHELL(4.32,4.18)
  round 0.8 hole 0.8 unplated: ""(-2.888,3.68) ""(2.891,3.679)
  silkscreen extent -4.47,-2.61 4.47,4.79

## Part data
C1 C2 C3 C4 C5 C6 C7 C8 C15 C16 C17 C18 C19 C20 C21 C22 C23 C24 C25 C26 C27 C28 C29 C30 C31 C32 C33: library part Cap, "Capacitor"
D1 D3: library part "D Schottky", "Schottky Diode"
J2: library part IDC40
J3 J4: library part RASPBERRY_PI
L1 L2: library part Inductor, "Inductor"
LED1 LED2: library part LED2, "Typical RED, GREEN, YELLOW, AMBER GaAs LED"
M1: library part F133_CORE
R1 R2 R3 R4 R5 R6 R7 R10 R11 R12 R13 R15 R16 R17 R18 R19 R20 R21 R22 R23 R24 R25 R26 R28 R29 R30 R33 R34 R35 R36 R37 R38 R39 R40: library part Res1, "Resistor"
X1: library part 24MHz_1

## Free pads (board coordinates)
  round 236.22 hole 129.92: 0(157.48,157.48) 0(157.48,2559.06) 0(2559.06,157.48) 0(2559.06,2559.06)

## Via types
v1: diameter 17.72, hole 7.87, Top Layer to Bottom Layer, tented both sides, 278 vias
v2: diameter 23.62, hole 11.81, Top Layer to Bottom Layer, tented both sides, 9 vias

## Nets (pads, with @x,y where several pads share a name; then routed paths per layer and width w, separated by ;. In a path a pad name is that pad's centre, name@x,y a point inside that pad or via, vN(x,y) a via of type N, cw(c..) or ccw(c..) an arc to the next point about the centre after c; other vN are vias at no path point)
AP_CK24M_OUT: J4.12 M1.22 | length 826.4
  Top Layer w8: M1.22@1823.57,963.57 cw(c1800.15,940.15) 1833.27,940.15 cw(c1866.38,940.15) M1.22@1842.97,963.57 ; M1.22@1833.27,968 1833.27,940 1865,908.27 J4.12@2566.54,908.27
AP_UART1_CTS: J4.8 M1.8 | length 2143.7
  Top Layer w6: M1.8@1122.86,1026.98 ccw(c1097.74,1052.1) 1133.27,1052.1 ccw(c1168.8,1052.1) M1.8@1143.67,1026.98 ; M1.8@1127.1,1022.74 ccw(c1112.22,1037.62) 1133.27,1037.62 ccw(c1154.31,1037.62) M1.8@1139.43,1022.74 ; v1@1128.86,1059.86 cw(c1118.21,1049.21) 1133.27,1049.21 ; v1(1133,1064) 1133.27,1063.73 M1.8@1133.27,994.92 ; 1133.27,1050.5 cw(c1146.5,1050.5) v1@1137.14,1059.86
  Bottom Layer w6: v1@1133,1058.14 cw(c1133,1044) 1143,1054 cw(c1153,1064) v1@1138.86,1064 ; v1(1133,1064) 1163,1034 2419.06,1034 2497.8,955.26 2497.8,777 J4.8@2566.54,708.27 ; J4.8@2538.04,708.27 ccw(c2469.24,708.27) 2517.89,756.91 ccw(c2566.54,805.56) J4.8@2566.54,736.76 ; J4.8@2544.04,708.27 ccw(c2489.73,708.27) 2528.13,746.67 ccw(c2566.54,785.07) J4.8@2566.54,730.76 ; J4.8@2550.04,708.27 ccw(c2510.21,708.27) 2538.37,736.43 ccw(c2566.54,764.59) J4.8@2566.54,724.76
AP_UART1_RTS: J4.7 M1.7 | length 2371.8
  Top Layer w6: M1.7@1072.86,1026.98 ccw(c1047.74,1052.1) 1083.27,1052.1 ccw(c1118.8,1052.1) M1.7@1093.67,1026.98 ; M1.7@1077.1,1022.74 ccw(c1062.22,1037.62) 1083.27,1037.62 ccw(c1104.31,1037.62) M1.7@1089.43,1022.74 ; v1@1078.86,1056.86 cw(c1068.21,1046.21) 1083.27,1046.21 ; v1(1083,1061) 1083.27,1060.73 M1.7@1083.27,994.92 ; 1083.27,1047.5 cw(c1096.5,1047.5) v1@1087.14,1056.86
  Bottom Layer w6: v1@1083,1055.14 cw(c1083,1041) 1093,1051 cw(c1103,1061) v1@1088.86,1061 ; v1(1083,1061) 1122,1022 2414.09,1022 2485.8,950.28 2485.8,701.2 2528,659 2617.27,659 J4.7@2666.54,708.27 ; J4.7@2638.04,708.27 cw(c2569.24,708.27) 2617.89,659.62 cw(c2666.54,610.98) J4.7@2666.54,679.77 ; J4.7@2644.04,708.27 cw(c2589.73,708.27) 2628.13,669.86 cw(c2666.54,631.46) J4.7@2666.54,685.77 ; J4.7@2650.04,708.27 cw(c2610.21,708.27) 2638.37,680.11 cw(c2666.54,651.95) J4.7@2666.54,691.77
AP_UART1_RXD: J4.5 M1.6 | length 2553
  Top Layer w6: M1.6@1022.86,1026.98 ccw(c997.74,1052.1) 1033.27,1052.1 ccw(c1068.8,1052.1) M1.6@1043.67,1026.98 ; M1.6@1027.1,1022.74 ccw(c1012.22,1037.62) 1033.27,1037.62 ccw(c1054.31,1037.62) M1.6@1039.43,1022.74 ; v1@1027.93,1057.07 cw(c1008.87,1046.07) 1030.12,1040.37 ; v1@1028.86,1055.86 cw(c1018.21,1045.21) 1033.27,1045.21 ; v1@1030.07,1054.93 cw(c1026.05,1047.96) 1033.82,1050.04 ; 1033,1051.11 cw(c1039.07,1049.49) v1@1035.93,1054.93 ; v1(1033,1060) 1033.27,1059.73 M1.6@1033.27,994.92 ; 1033.27,1046.5 cw(c1046.5,1046.5) v1@1037.14,1055.86 ; 1036.05,1041.71 cw(c1055.6,1046.95) v1@1038.07,1057.07
  Bottom Layer w6: v1@1033,1054.14 cw(c1033,1040) 1043,1050 cw(c1053,1060) v1@1038.86,1060 ; v1(1033,1060) 1083,1010 2409.12,1010 2473.8,945.31 2473.8,619.2 2536,557 2615.27,557 J4.5@2666.54,608.27 ; J4.5@2638.04,608.27 cw(c2569.24,608.27) 2617.89,559.62 cw(c2666.54,510.98) J4.5@2666.54,579.77 ; J4.5@2644.04,608.27 cw(c2589.73,608.27) 2628.13,569.86 cw(c2666.54,531.46) J4.5@2666.54,585.77 ; J4.5@2650.04,608.27 cw(c2610.21,608.27) 2638.37,580.11 cw(c2666.54,551.95) J4.5@2666.54,591.77
AP_UART1_TXD: J4.3 M1.5 | length 2695.2
  Top Layer w6: M1.5@972.86,1026.98 ccw(c947.74,1052.1) 983.27,1052.1 ccw(c1018.8,1052.1) M1.5@993.67,1026.98 ; M1.5@977.1,1022.74 ccw(c962.22,1037.62) 983.27,1037.62 ccw(c1004.31,1037.62) M1.5@989.43,1022.74 ; v1@977.93,1057.07 cw(c958.87,1046.07) 980.12,1040.37 ; v1@978.86,1055.86 cw(c968.21,1045.21) 983.27,1045.21 ; v1@980.07,1054.93 cw(c976.05,1047.96) 983.82,1050.04 ; 983,1051.11 cw(c989.07,1049.49) v1@985.93,1054.93 ; v1(983,1060) 983.27,1059.73 M1.5@983.27,994.92 ; 983.27,1046.5 cw(c996.5,1046.5) v1@987.14,1055.86 ; 986.05,1041.71 cw(c1005.6,1046.95) v1@988.07,1057.07
  Bottom Layer w6: v1@983,1054.14 cw(c983,1040) 993,1050 cw(c1003,1060) v1@988.86,1060 ; v1(983,1060) 1045,998 2404.15,998 2461.8,940.34 2461.8,518.2 2520,460 2618.27,460 ; J4.3@2638.04,508.11 cw(c2570.54,507.73) 2618.27,460 ; J4.3@2644.04,508.14 cw(c2590.75,507.85) 2628.43,470.16 cw(c2666.11,432.48) J4.3@2666.41,485.77 ; J4.3@2650.04,508.18 cw(c2610.96,507.96) 2638.6,480.33 cw(c2666.23,452.7) J4.3@2666.44,491.77 ; J4.3@2666.38,479.77 ccw(c2666,412.27) 2618.27,460 ; J4.3@2666.54,508.27 2618.27,460
AP_WAKE_BT: J3.37 M1.94 | length 1581.6
  Top Layer w6: v1(372,1190) 688.19,1190 M1.94@688.98,1189.21 ; v1@376.14,1185.86 cw(c386.14,1175.86) 386.14,1190 cw(c386.14,1204.14) v1@376.14,1194.14 ; 629.89,1190 cw(c629.89,1151.78) M1.94@656.92,1178.81 ; 633.69,1190 ccw(c633.69,1222.84) M1.94@656.92,1199.62 ; 644.38,1190 cw(c644.38,1166.27) M1.94@661.16,1183.05 ; 648.18,1190 ccw(c648.18,1208.36) M1.94@661.16,1195.38
  Bottom Layer w6: J3.37@50,508.27 99.73,558 168,558 229,619 229,763.09 288,822.09 288,1140.03 337.97,1190 v1(372,1190) ; J3.37@50,524.76 ccw(c50,564.59) 78.16,536.43 ccw(c106.32,508.27) J3.37@66.5,508.27 ; J3.37@50,530.76 ccw(c50,585.07) 88.4,546.67 ccw(c126.81,508.27) J3.37@72.5,508.27 ; J3.37@50,536.76 ccw(c50,605.56) 98.65,556.91 ccw(c147.29,508.27) J3.37@78.5,508.27 ; v1@367.86,1185.86 ccw(c357.86,1175.86) 357.86,1190 ccw(c357.86,1204.14) v1@367.86,1194.14
AVDD15: C29.2 C30.2 U3.18 | length 250.7
  Top Layer w8: U3.18@1704.29,702.13 1704.29,721.79 1708.93,726.44 1768.93,726.44 v1(1789.58,747.09) ; v1@1784.72,747.09 cw(c1773,747.09) 1781.29,738.8 cw(c1789.58,730.5) v1@1789.58,742.23
  Top Layer w20: v1(1789.58,747.09) C30.2@1789.58,774.96
  Bottom Layer w8: C29.2@1784.4,769.78 cw(c1771.88,757.26) 1789.58,757.26 ; v1@1786.15,750.53 ccw(c1777.85,758.82) 1789.58,758.82 ccw(c1801.31,758.82) v1@1793.02,750.53 ; v1(1789.58,747.09) 1789.58,774.96 C29.2@1789.92,775.3 ; v1@1789.58,755.63 cw(c1809.6,755.63) C29.2@1795.44,769.78 ; 1791.27,761.94 ccw(c1804.92,758.28) v1@1793.51,749.95
AVDDRF: C23.2 C27.2 C28.2 L2.1 U3.8 U3.19 | length 901.2
  Top Layer w8: U3.19@1688.55,702.13 1688.55,738.05 1700.58,750.09 v1(1748.58,750.09) ; U3.8@1720.04,540.17 v1(1748.58,540.09) ; 1736.65,540.17 cw(c1736.65,528.16) v1@1745.15,536.65 ; 1737.05,540.17 ccw(c1737.05,551.62) v1@1745.15,543.53 ; v1@1745.15,746.65 ccw(c1736.85,738.36) 1736.85,750.09 ccw(c1736.85,761.82) v1@1745.15,753.53
  Top Layer w20: v1@1747.86,540.97 cw(c1756.23,530.74) 1765.58,540.09 ; v1(1748.58,540.09) 1765.58,540.09 ; v1@1748.58,541.23 cw(c1748.58,502.95) 1775.65,530.02 ; v1(1748.58,750.09) 1748.58,773.96 C27.2@1749.92,775.3 ; 1872.8,406.87 ccw(c1929.92,464) L2.1@1929.92,383.21 ; L2.1@1929.92,363.69 1915.99,363.69 1819.68,459.99 C23.2@1794.92,459.99 1794.92,510.75 1765.58,540.09
  Bottom Layer w8: C28.2@1744.4,769.78 cw(c1734.3,759.68) 1748.58,759.68 ; v1@1745.15,753.53 ccw(c1736.85,761.82) 1748.58,761.82 ccw(c1760.31,761.82) v1@1752.02,753.53 ; v1@1746.15,754.3 ccw(c1741.67,762.06) 1750.33,759.74 ; v1(1748.58,750.09) C28.2@1748.58,766.09 ; v1@1748.58,753.21 cw(c1772.01,753.21) C28.2@1755.44,769.78 ; C28.2@1751.34,763.51 ccw(c1765.34,759.76) v1@1752.79,752.52 ; C28.2@1748.58,766.09 1748.58,773.96 C28.2@1749.92,775.3 1749.92,767.43 C28.2@1748.58,766.09
  Bottom Layer w20: v1(1748.58,540.09) v1(1748.58,750.09)
BL702_DM: D22.2 DEBUG.A7 DEBUG.B7 R25.2 | length 681.7
  Top Layer w6: DEBUG.B7@1618.54,273.72 cw(c1613.58,268.76) 1620.59,268.76 cw(c1627.6,268.76) DEBUG.B7@1622.64,273.72 ; DEBUG.B7@1620.59,298.22 1620.59,260.1 1613.58,253.09 1613.58,231.09 1640.58,204.09 1673.58,204.09 1677.58,208.09 v1(1692.58,208.09) ; v1@1688.44,203.95 ccw(c1678.44,193.95) 1678.44,208.09 ccw(c1678.44,222.23) v1@1688.44,212.23
  Top Layer w6.69: v1@1656.68,240.99 ccw(c1648.78,248.89) 1659.96,248.89 ; DEBUG.A7@1658.15,273.97 cw(c1653.78,269.6) 1659.96,269.6 cw(c1666.14,269.6) DEBUG.A7@1661.77,273.97 ; DEBUG.A7@1658.15,322.47 ccw(c1653.78,326.84) 1659.96,326.84 ccw(c1666.14,326.84) DEBUG.A7@1661.77,322.47 ; 1659.96,251.9 ccw(c1675.39,251.9) v1@1664.48,240.99 ; v1(1660.58,237.09) 1659.96,237.71 DEBUG.A7@1659.96,298.22 1659.96,405.66 R25.2@1674.92,420.62 ; R25.2@1666.46,420.62 cw(c1646.02,420.62) 1660.47,406.17 cw(c1674.92,391.72) R25.2@1674.92,412.15
  Bottom Layer w6.69: v1@1656.68,233.19 cw(c1647.28,223.78) 1660.58,223.78 cw(c1673.89,223.78) v1@1664.48,233.19 ; v1@1657.83,232.32 cw(c1651.17,220.79) 1664.03,224.24 cw(c1676.88,227.68) v1@1665.36,234.33 ; 1660.58,221.67 ccw(c1678.09,221.67) D22.2@1666.13,208.88 ; D22.2@1670.7,213.77 cw(c1692.51,237.09) v1(1660.58,237.09) 1660.58,211.92 D22.2@1664.92,207.59 1692.08,207.59 v1(1692.58,208.09) ; D22.2@1670.91,201.6 cw(c1685.36,187.15) 1685.36,207.59 cw(c1685.36,228.02) D22.2@1670.91,213.57 ; 1677.45,205.47 cw(c1681.31,191.08) v1@1689.54,203.5 ; 1678.06,207.59 ccw(c1678.06,222.61) v1@1688.68,211.99 ; 1679.08,209.27 ccw(c1681.6,218.67) v1@1688.61,211.92 ; 1680.49,207.59 cw(c1680.49,196) v1@1688.68,204.19 ; 1682.6,206.85 ccw(c1680.38,215.14) v1@1687.81,210.85
BL702_DP: D23.2 DEBUG.A6 DEBUG.B6 R26.2 | length 660.3
  Top Layer w6: v1@1629.44,238.95 cw(c1619.44,228.95) 1633.58,228.95 cw(c1647.73,228.95) v1@1637.72,238.95 ; v1@1629.44,247.23 ccw(c1603.28,273.39) DEBUG.A6@1640.28,273.39 ; v1@1633.68,242.99 ccw(c1617.77,258.91) 1640.28,258.91 ; DEBUG.A6@1638.22,273.72 cw(c1633.26,268.76) 1640.28,268.76 cw(c1647.29,268.76) DEBUG.A6@1642.33,273.72 ; DEBUG.A6@1640.28,298.22 1640.28,247.78 1635.58,243.09 v1(1633.58,243.09) 1633.58,228.09 1644.58,217.09 1666.58,217.09 1679.65,230.15 DEBUG.B6@1679.65,298.22 ; DEBUG.B6@1677.59,273.72 cw(c1672.63,268.76) 1679.65,268.76 cw(c1686.66,268.76) DEBUG.B6@1681.7,273.72
  Top Layer w6.69: R26.2@1628.94,414.63 cw(c1584.68,370.38) 1647.27,370.38 ; R26.2@1633.67,419.36 cw(c1600.84,386.53) 1647.27,386.53 ; R26.2@1634.92,420.62 1647.27,408.27 ; R26.2@1635.91,412.21 cw(c1637.53,398.53) 1647.27,408.27 ; R26.2@1638.4,424.1 cw(c1617,402.69) 1647.27,402.69 ; DEBUG.A6@1638.47,322.47 ccw(c1634.1,326.84) 1640.28,326.84 ccw(c1646.45,326.84) DEBUG.A6@1642.08,322.47 ; DEBUG.A6@1640.28,298.22 1640.28,335.78 1647.27,342.78 1647.27,408.27 ; R26.2@1643.33,419.63 ccw(c1657.01,418.01) 1647.27,408.27
  Bottom Layer w6: D23.2@1613.69,213.82 ccw(c1598.65,228.86) 1619.92,228.86 ccw(c1641.19,228.86) D23.2@1626.15,213.82 ; D23.2@1619.92,207.59 1619.92,229.43 v1(1633.58,243.09) ; v1@1627.72,243.09 cw(c1613.58,243.09) 1623.58,233.09 cw(c1633.58,223.09) v1@1633.58,237.23
BL702_DTR: R39.1 R40.1 U3.31 | length 225.8
  Top Layer w6: R39.1@1508.38,551.53 ccw(c1493.33,566.57) 1514.61,566.57 ccw(c1535.88,566.57) R39.1@1520.84,551.53 ; R40.1@1508.38,579.07 cw(c1493.33,564.03) 1514.61,564.03 cw(c1535.88,564.03) 1520.84,579.07 cw(c1527.38,572.53) 1527.38,581.78 ; R39.1@1514.61,545.3 R40.1@1514.61,585.3 1518.13,581.78 U3.31@1583.94,581.78 ; R40.1@1516.59,587.29 ccw(c1529.89,600.59) 1529.89,581.78 ; R40.1@1520.84,591.53 ccw(c1544.38,615.07) 1544.38,581.78
BL702_JTAG_TCK: R33.2 U3.23 | length 143.6
  Top Layer w6: R33.2@1568.69,769.39 cw(c1553.65,754.35) 1574.92,754.35 cw(c1596.19,754.35) R33.2@1581.15,769.39 ; R33.2@1574.92,775.62 1574.92,748.75 1583.58,740.09 1610.45,740.09 1625.55,724.99 U3.23@1625.55,702.13
BL702_JTAG_TDI: R34.2 U3.1 | length 179
  Top Layer w6: R34.2@1514.92,459.99 1551.02,496.09 1595.58,496.09 1609.81,510.31 U3.1@1609.81,540.17 ; R34.2@1514.92,468.8 ccw(c1514.92,490.07) 1529.96,475.03 ccw(c1545,459.99) R34.2@1523.73,459.99
BL702_JTAG_TDO: R35.2 U3.2 | length 155.5
  Top Layer w6: R35.2@1554.92,459.99 1579.02,484.09 1600.58,484.09 1625.55,509.05 U3.2@1625.55,540.17 ; R35.2@1554.92,468.8 ccw(c1554.92,490.07) 1569.96,475.03 ccw(c1585,459.99) R35.2@1563.73,459.99
BL702_JTAG_TMS: R36.2 U3.3 | length 132.8
  Top Layer w6: R36.2@1594.92,459.99 1641.3,506.36 U3.3@1641.3,540.17 ; R36.2@1594.92,468.8 ccw(c1594.92,490.07) 1609.96,475.03 ccw(c1625,459.99) R36.2@1603.73,459.99
BL702_U1RX: J4.16 M1.27 U3.30 | length 2187.6
  Top Layer w6: v1@1523.58,610.23 cw(c1523.58,596.09) 1533.58,606.09 cw(c1543.58,616.09) v1@1529.44,616.09 ; v1(1523.58,616.09) 1542.14,597.53 U3.30@1583.94,597.53
  Top Layer w8: M1.27@2027.56,1189.21 2192,1189.21 2251,1130.21 v1(2251,974) 2263,962 2328,962 2337,971 2343,977 2343,1025 2396,1078 2536.27,1078 ; M1.27@2058.91,1179.51 cw(c2082.33,1156.1) 2082.33,1189.21 cw(c2082.33,1222.33) M1.27@2058.91,1198.91 ; v1@2247.56,977.44 ccw(c2239.27,985.73) 2251,985.73 ccw(c2262.73,985.73) v1@2254.44,977.44 ; v1@2251,969.14 cw(c2251,957.41) 2259.29,965.71 cw(c2267.59,974) v1@2255.86,974 ; J4.16@2540.77,1098.67 cw(c2522.43,1091.84) 2536.27,1078 ; J4.16@2556.94,1082.5 ccw(c2550.11,1064.16) 2536.27,1078 ; J4.16@2566.54,1108.27 2536.27,1078
  Bottom Layer w6: v1@1519.44,620.23 ccw(c1509.44,630.23) 1523.58,630.23 ccw(c1537.73,630.23) v1@1527.72,620.23 ; v1(1523.58,616.09) 1523.58,652.09 1562.58,691.09 1562.58,749.42 1528,784 1528,948 1566,986 2239,986 v1(2251,974) ; v1@2245.14,974 ccw(c2231,974) 2241,984 ccw(c2251,994) v1@2251,979.86
BL702_U1TX: J4.15 M1.26 U3.29 | length 2324.6
  Top Layer w6: v1@1543.58,625.23 cw(c1543.58,611.09) 1553.58,621.09 cw(c1563.58,631.09) v1@1549.44,631.09 ; v1(1543.58,631.09) 1561.39,613.28 U3.29@1583.94,613.28
  Top Layer w8: M1.26@2027.56,1139.21 2194,1139.21 2222,1111.21 v1(2222,963) 2239,946 2343,946 2360,963 2360,1017 2404,1061 2619.27,1061 J4.15@2666.54,1108.27 ; M1.26@2058.91,1129.51 cw(c2082.33,1106.1) 2082.33,1139.21 cw(c2082.33,1172.33) M1.26@2058.91,1148.91 ; v1@2218.56,966.44 ccw(c2210.27,974.73) 2222,974.73 ccw(c2233.73,974.73) v1@2225.44,966.44 ; v1@2222,958.14 cw(c2222,946.41) 2230.29,954.71 cw(c2238.59,963) v1@2226.86,963 ; J4.15@2639.04,1108.27 cw(c2572.66,1108.27) 2619.6,1061.33 cw(c2666.54,1014.39) J4.15@2666.54,1080.77 ; J4.15@2647.04,1108.27 cw(c2599.97,1108.27) 2633.25,1074.99 cw(c2666.54,1041.7) J4.15@2666.54,1088.77
  Bottom Layer w6: v1@1539.44,635.23 ccw(c1529.44,645.23) 1543.58,645.23 ccw(c1557.73,645.23) v1@1547.72,635.23 ; v1(1543.58,631.09) 1543.58,655.12 1574.58,686.12 1574.58,754.42 1540,789 1540,943.03 1570.97,974 2211,974 v1(2222,963) ; v1@2216.14,963 ccw(c2202,963) 2212,973 ccw(c2222,983) v1@2222,968.86
BL702_VBUS: C18.2 C21.2 D1.1 D21.2 DEBUG.A4B9 DEBUG.B4A9 U3.6 | length 455.3
  Top Layer w8: U3.6@1688.55,540.17 1688.55,510.13 v1(1714.92,483.75) C18.2@1714.92,459.99 ; C18.2@1709.4,465.51 ccw(c1696.06,478.85) 1714.92,478.85 ccw(c1733.78,478.85) C18.2@1720.44,465.51 ; v1@1710.06,483.75 ccw(c1698.33,483.75) 1706.63,492.05 ccw(c1714.92,500.34) v1@1714.92,488.61 ; v1@1711.09,480.76 cw(c1702.77,474.27) C18.2@1712.96,471.54 ; v1@1711.49,480.32 cw(c1703.19,472.02) 1714.92,472.02 cw(c1726.65,472.02) v1@1718.36,480.32 ; C18.2@1716.88,471.54 cw(c1727.07,474.27) v1@1718.75,480.76
  Top Layer w20: DEBUG.A4B9@1555.63,298.22 1555.63,346.04 v1(1555.58,346.09) v1(1578.58,369.09) ; DEBUG.B4A9@1744.61,298.22 1744.61,344.07 v1(1744.58,376.09)
  Bottom Layer w20: v1(1714.92,483.75) 1744.58,454.09 v1(1744.58,376.09)
  other v1: 1744.58,344.09
BL702_VDD_CORE: C20.2 U3.7 | length 142.7
  Top Layer w8: U3.7@1704.29,540.17 1704.29,519.09 1721.29,502.09 1741.58,502.09 1754.92,488.75 C20.2@1754.92,459.99 ; C20.2@1749.4,465.51 ccw(c1736.06,478.85) 1754.92,478.85 ccw(c1773.78,478.85) C20.2@1760.44,465.51
BT_RST_N: J3.40 M1.96 | length 1245.9
  Top Layer w6: v1(371,1089) 371.21,1089.21 M1.96@688.98,1089.21 ; v1@375.14,1084.86 cw(c385.66,1074.34) 385.66,1089.21 ; v1@375.14,1093.14 ccw(c384.63,1102.63) 384.63,1089.21 ; M1.96@656.92,1078.81 ccw(c631.79,1053.68) 631.79,1089.21 ccw(c631.79,1124.74) M1.96@656.92,1099.62 ; M1.96@661.16,1083.05 ccw(c646.28,1068.17) 646.28,1089.21 ccw(c646.28,1110.26) M1.96@661.16,1095.38
  Bottom Layer w6: J3.40@150,408.27 204,462.27 204,545 253,594 253,753.15 312,812.15 312,1068 333,1089 v1(371,1089) ; v1@366.86,1084.86 ccw(c356.86,1074.86) 356.86,1089 ccw(c356.86,1103.14) v1@366.86,1093.14
BT_WAKE_AP: J3.38 M1.95 | length 1453
  Top Layer w6: v1(372,1139) 372.21,1139.21 M1.95@688.98,1139.21 ; v1@376.14,1134.86 cw(c386.66,1124.34) 386.66,1139.21 ; v1@376.14,1143.14 ccw(c385.63,1152.63) 385.63,1139.21 ; M1.95@656.92,1128.81 ccw(c631.79,1103.68) 631.79,1139.21 ccw(c631.79,1174.74) M1.95@656.92,1149.62 ; M1.95@661.16,1133.05 ccw(c646.28,1118.17) 646.28,1139.21 ccw(c646.28,1160.26) M1.95@661.16,1145.38
  Bottom Layer w6: J3.38@150,508.27 241,599.27 241,758.12 300,817.12 300,1108 331,1139 v1(372,1139) ; J3.38@150,524.76 ccw(c150,564.59) 178.16,536.43 ccw(c206.32,508.27) J3.38@166.5,508.27 ; J3.38@150,530.76 ccw(c150,585.07) 188.4,546.67 ccw(c226.81,508.27) J3.38@172.5,508.27 ; J3.38@150,536.76 ccw(c150,605.56) 198.65,556.91 ccw(c247.29,508.27) J3.38@178.5,508.27 ; v1@367.86,1134.86 ccw(c357.86,1124.86) 357.86,1139 ccw(c357.86,1153.14) v1@367.86,1143.14
CK_N: J2.6 M1.46 | length 684.3
  Top Layer w6: J2.6@1948.82,2559.06 2007.87,2500 2055.09,2500 2105,2450.09 2105,2153 2091.21,2139.21 M1.46@2027.56,2139.21 ; J2.6@1948.82,2578.74 J2.6@1958.66,2568.9 ; M1.46@2055.38,2133.05 cw(c2070.26,2118.17) 2070.26,2139.21 cw(c2070.26,2160.26) M1.46@2055.38,2145.38 ; M1.46@2059.62,2128.81 cw(c2084.74,2103.68) 2084.74,2139.21 cw(c2084.74,2174.74) M1.46@2059.62,2149.62
CK_P: J2.5 M1.45 | length 897.4
  Top Layer w6: J2.5@1948.82,2657.48 1988,2618.3 ; J2.5@1957,2628.27 cw(c1967.48,2616.08) 1978.85,2627.45 ; J2.5@1960.92,2623.72 cw(c1971.71,2611.16) 1983.42,2622.87 ; J2.5@1964.83,2619.17 cw(c1975.94,2606.24) 1988,2618.3 ; J2.5@1973.38,2637.8 ccw(c1985.14,2637.8) 1976.82,2629.47 ; M1.45@2027.56,2089.21 2082.21,2089.21 ; M1.45@2055.7,2083.39 cw(c2068.76,2071.66) 2068.76,2089.21 cw(c2068.76,2106.77) M1.45@2055.7,2095.04 ; M1.45@2060.16,2079.38 cw(c2082.21,2059.57) 2082.21,2089.21 ; M1.45@2060.16,2099.05 ccw(c2082.21,2118.85) 2082.21,2089.21 ; 1988,2618.3 1988,2536.84 2012.84,2512 2060.06,2512 2117,2455.06 2117,2124 2082.21,2089.21
CLK_FANOUT: J4.11 M1.10 | length 1936.7
  Top Layer w6: M1.10@1222.86,1026.98 ccw(c1197.74,1052.1) 1233.27,1052.1 ccw(c1268.8,1052.1) M1.10@1243.67,1026.98 ; M1.10@1227.1,1022.74 ccw(c1212.22,1037.62) 1233.27,1037.62 ccw(c1254.31,1037.62) M1.10@1239.43,1022.74 ; v1@1229.13,1061.86 cw(c1219.12,1051.86) 1233.27,1051.86 cw(c1247.41,1051.86) v1@1237.41,1061.86 ; M1.10@1233.27,994.92 v1(1233.27,1066)
  Bottom Layer w6: v1(1233.27,1066) 1241.27,1058 2429,1058 2530,957 2617.8,957 J4.11@2666.54,908.27 ; J4.11@2638.04,908.27 ccw(c2569.24,908.27) 2617.89,956.91 ccw(c2666.54,1005.56) J4.11@2666.54,936.76 ; J4.11@2644.04,908.27 ccw(c2589.73,908.27) 2628.13,946.67 ccw(c2666.54,985.07) J4.11@2666.54,930.76 ; J4.11@2650.04,908.27 ccw(c2610.21,908.27) 2638.37,936.43 ccw(c2666.54,964.59) J4.11@2666.54,924.76
CTP_INT: J2.21 M1.67 | length 795.2
  Top Layer w6: M1.67@1022.86,2365.56 ccw(c997.74,2390.69) 1033.27,2390.69 ccw(c1068.8,2390.69) M1.67@1043.67,2365.56 ; M1.67@1027.1,2361.32 ccw(c1012.22,2376.2) 1033.27,2376.2 ccw(c1054.31,2376.2) M1.67@1039.43,2361.32 ; M1.67@1033.27,2333.5 1033.27,2457.3 1081.97,2506 1327,2506 1359,2538 1359,2617.38 ; J2.21@1318.9,2657.48 1359,2617.38 ; J2.21@1326.79,2628.02 cw(c1337.5,2614.75) 1349.56,2626.81 ; J2.21@1330.55,2623.36 cw(c1341.72,2609.53) 1354.28,2622.1 ; J2.21@1334.32,2618.69 cw(c1345.93,2604.31) 1359,2617.38 ; J2.21@1343.45,2637.8 ccw(c1355.22,2637.8) 1346.9,2629.47
CTP_RST: J2.22 M1.68 | length 819.2
  Top Layer w6: M1.68@972.86,2365.56 ccw(c947.74,2390.69) 983.27,2390.69 ccw(c1018.8,2390.69) M1.68@993.67,2365.56 ; M1.68@977.1,2361.32 ccw(c962.22,2376.2) 983.27,2376.2 ccw(c1004.31,2376.2) M1.68@989.43,2361.32 ; M1.68@983.27,2333.5 983.27,2424.27 1077,2518 1258.16,2518 ; 1266.09,2525.94 cw(c1304.63,2487.4) J2.22@1315.27,2540.85 ; 1274.03,2533.87 cw(c1307.27,2500.64) J2.22@1316.44,2546.74 ; 1281.97,2541.81 cw(c1309.9,2513.87) J2.22@1317.62,2552.62 ; 1289.9,2549.75 cw(c1312.54,2527.11) J2.22@1318.79,2558.51 ; 1290.89,2550.73 ccw(c1282.57,2559.06) J2.22@1294.34,2559.06 ; J2.22@1314.1,2534.97 ccw(c1302,2474.16) 1258.16,2518 ; J2.22@1318.9,2578.74 1258.16,2518
D0_N: J2.2 M1.42 | length 906.2
  Top Layer w6: M1.42@2027.56,1939.21 2081,1939.21 ; M1.42@2055.86,1933.57 cw(c2068.04,1923.24) 2068.04,1939.21 cw(c2068.04,1955.19) M1.42@2055.86,1944.85 ; M1.42@2060.43,1929.69 cw(c2081,1912.24) 2081,1939.21 ; M1.42@2060.43,1948.73 ccw(c2081,1966.18) 2081,1939.21 ; J2.2@2094.09,2537.75 cw(c2082.01,2516.67) 2106.3,2516.67 ; J2.2@2097.07,2542.95 cw(c2087.94,2527.03) 2106.3,2527.03 cw(c2124.65,2527.03) J2.2@2115.53,2542.95 ; J2.2@2106.3,2578.74 2106.3,2516.67 ; J2.2@2118.51,2537.75 ccw(c2130.59,2516.67) 2106.3,2516.67 ; 2081,1939.21 2153,2011.21 2153,2469.97 2106.3,2516.67
D0_P: J2.1 M1.41 | length 1056.3
  Top Layer w6: M1.41@2027.56,1889.21 2078,1889.21 ; M1.41@2061.14,1880.59 cw(c2078,1868.42) 2078,1889.21 ; M1.41@2061.14,1897.83 ccw(c2078,1910.01) 2078,1889.21 ; J2.1@2106.3,2657.48 2152,2611.78 ; J2.1@2109.52,2632.08 cw(c2120.05,2613.38) 2135.22,2628.55 ; J2.1@2112.46,2626.85 cw(c2124.07,2606.22) 2140.82,2622.96 ; J2.1@2115.4,2621.62 cw(c2128.1,2599.07) 2146.41,2617.37 ; J2.1@2118.35,2616.39 cw(c2132.13,2591.91) 2152,2611.78 ; J2.1@2130.86,2637.8 ccw(c2142.62,2637.8) 2134.3,2629.47 ; 2078,1889.21 2165,1976.21 2165,2474.94 2152,2487.94 2152,2611.78
D1_N: J2.4 M1.44 | length 675.2
  Top Layer w6: J2.4@2027.56,2559.06 2029.97,2559.06 2129,2460.03 2129,2091 2077.21,2039.21 ; J2.4@2027.56,2578.74 2027.56,2561.47 J2.4@2028.77,2560.26 ; M1.44@2043,2039.21 2077.21,2039.21 ; M1.44@2061.33,2030.87 cw(c2077.21,2019.94) 2077.21,2039.21 ; M1.44@2061.33,2047.56 ccw(c2077.21,2058.49) 2077.21,2039.21
D1_P: J2.3 M1.43 | length 937.2
  Top Layer w6: J2.3@2027.56,2657.48 2067,2618.04 ; J2.3@2035.66,2628.2 cw(c2046.21,2615.71) 2057.77,2627.27 ; J2.3@2039.53,2623.62 cw(c2050.43,2610.71) 2062.38,2622.65 ; M1.43@2043,1989.21 2081,1989.21 ; J2.3@2043.4,2619.03 cw(c2054.66,2605.7) 2067,2618.04 ; J2.3@2052.12,2637.8 ccw(c2063.88,2637.8) 2055.56,2629.47 ; M1.43@2055.86,1983.57 cw(c2068.04,1973.24) 2068.04,1989.21 cw(c2068.04,2005.19) M1.43@2055.86,1994.85 ; M1.43@2060.43,1979.69 cw(c2081,1962.24) 2081,1989.21 ; M1.43@2060.43,1998.73 ccw(c2081,2016.18) 2081,1989.21 ; 2067,2618.04 2067,2539 2141,2465 2141,2049.21 2081,1989.21
D2_N: J2.8 M1.49 | length 340.6
  Top Layer w6: J2.8@1870.08,2559.06 1933.27,2495.87 M1.49@1933.27,2333.5 ; M1.49@1922.86,2365.56 ccw(c1897.74,2390.69) 1933.27,2390.69 ccw(c1968.8,2390.69) M1.49@1943.67,2365.56 ; M1.49@1927.1,2361.32 ccw(c1912.22,2376.2) 1933.27,2376.2 ccw(c1954.31,2376.2) M1.49@1939.43,2361.32
D2_P: J2.7 M1.48 | length 771.8
  Top Layer w6: J2.7@1870.08,2657.48 1909,2618.56 ; J2.7@1878.35,2628.34 cw(c1888.76,2616.45) 1899.93,2627.63 ; J2.7@1882.3,2623.83 cw(c1892.99,2611.62) 1904.46,2623.09 ; J2.7@1886.25,2619.31 cw(c1897.22,2606.78) 1909,2618.56 ; J2.7@1894.64,2637.8 ccw(c1906.4,2637.8) 1898.08,2629.47 ; M1.48@2027.56,2239.21 2079.21,2239.21 ; M1.48@2056.11,2233.88 cw(c2066.98,2225.46) 2066.98,2239.21 cw(c2066.98,2252.96) M1.48@2056.11,2244.55 ; M1.48@2060.85,2230.21 cw(c2079.21,2215.99) 2079.21,2239.21 ; M1.48@2060.85,2248.22 ccw(c2079.21,2262.43) 2079.21,2239.21 ; 1909,2618.56 1909,2537.1 1958.1,2488 2050.12,2488 2093,2445.12 2093,2253 2079.21,2239.21
D3_N: J2.10 M1.51 | length 331.8
  Top Layer w6: J2.10@1791.34,2559.06 1833.27,2517.12 M1.51@1833.27,2333.5 ; M1.51@1822.86,2365.56 ccw(c1797.74,2390.69) 1833.27,2390.69 ccw(c1868.8,2390.69) M1.51@1843.67,2365.56 ; M1.51@1827.1,2361.32 ccw(c1812.22,2376.2) 1833.27,2376.2 ccw(c1854.31,2376.2) M1.51@1839.43,2361.32
D3_P: J2.9 M1.50 | length 536.4
  Top Layer w6: J2.9@1791.34,2657.48 1831,2617.82 ; J2.9@1799.37,2628.14 cw(c1809.97,2615.39) 1821.7,2627.12 ; J2.9@1803.21,2623.53 cw(c1814.2,2610.31) 1826.35,2622.47 ; J2.9@1807.04,2618.91 cw(c1818.42,2605.24) 1831,2617.82 ; J2.9@1815.9,2637.8 ccw(c1827.66,2637.8) 1819.34,2629.47 ; M1.50@1872.86,2365.56 ccw(c1847.74,2390.69) 1883.27,2390.69 ccw(c1918.8,2390.69) M1.50@1893.67,2365.56 ; M1.50@1877.1,2361.32 ccw(c1862.22,2376.2) 1883.27,2376.2 ccw(c1904.31,2376.2) M1.50@1889.43,2361.32 ; M1.50@1883.27,2333.5 1883.27,2484.09 1831,2536.36 1831,2617.82
DC_CTRL: J2.19 M1.38 | length 1743
  Top Layer w6: v1(1437,1739) 1437.21,1739.21 M1.38@2027.56,1739.21 ; v1@1441.14,1734.86 cw(c1451.66,1724.34) 1451.66,1739.21 ; v1@1441.14,1743.14 ccw(c1450.63,1752.63) 1450.63,1739.21 ; M1.38@1995.5,1728.81 ccw(c1970.38,1703.68) 1970.38,1739.21 ccw(c1970.38,1774.74) M1.38@1995.5,1749.62 ; M1.38@1999.74,1733.05 ccw(c1984.86,1718.17) 1984.86,1739.21 ccw(c1984.86,1760.26) M1.38@1999.74,1745.38
  Bottom Layer w6: J2.19@1397.64,2657.48 1437,2618.12 ; J2.19@1405.77,2628.22 cw(c1416.29,2615.82) 1427.79,2627.32 ; J2.19@1409.65,2623.65 cw(c1420.52,2610.84) 1432.4,2622.72 ; J2.19@1413.53,2619.07 cw(c1424.75,2605.87) 1437,2618.12 ; J2.19@1422.2,2637.8 ccw(c1433.96,2637.8) 1425.64,2629.47 ; v1@1432.86,1743.14 ccw(c1422.86,1753.14) 1437,1753.14 ccw(c1451.14,1753.14) v1@1441.14,1743.14 ; v1(1437,1739) 1437,2618.12
DM_P0: D7.2 OTG.A7 OTG.B7 R11.1 | length 486.3
  Top Layer w6.69: OTG.B7@1033.78,273.97 cw(c1029.41,269.6) 1035.59,269.6 cw(c1041.77,269.6) OTG.B7@1037.4,273.97 ; OTG.B7@1035.59,298.22 1035.59,256.08 1043.58,248.09 1067.58,248.09 1074.96,255.47 OTG.A7@1074.96,298.22 1074.96,353.77 D7.2@1049.92,378.81 1073.58,402.47 1073.58,481.96 R11.1@1054.92,500.62 ; D7.2@1049.92,370.34 cw(c1049.92,349.91) 1064.37,364.36 cw(c1078.82,378.81) 1058.39,378.81 cw(c1078.82,378.81) 1064.37,393.26 cw(c1049.92,407.71) D7.2@1049.92,387.27 ; R11.1@1054.92,492.15 cw(c1054.92,471.72) 1069.37,486.17 cw(c1083.82,500.62) R11.1@1063.39,500.62 ; OTG.A7@1073.15,273.97 cw(c1068.78,269.6) 1074.96,269.6 cw(c1081.14,269.6) OTG.A7@1076.77,273.97 ; OTG.A7@1073.15,322.47 ccw(c1068.78,326.84) 1074.96,326.84 ccw(c1081.14,326.84) OTG.A7@1076.77,322.47
DP_P0: D8.2 OTG.A6 OTG.B6 R10.1 | length 538.2
  Top Layer w6.69: v1@1050.68,344.19 cw(c1039.6,333.11) 1055.28,333.11 ; OTG.A6@1053.47,322.47 ccw(c1049.1,326.84) 1055.28,326.84 ccw(c1061.45,326.84) OTG.A6@1057.08,322.47 ; v1(1054.58,348.09) 1055.28,347.4 OTG.A6@1055.28,298.22 ; 1055.28,336.46 cw(c1066.22,336.46) v1@1058.48,344.19 ; v1@1090.68,344.19 cw(c1081.12,334.63) 1094.65,334.63 ; v1@1090.68,351.99 ccw(c1081.12,361.55) 1094.65,361.55 ; OTG.B6@1092.84,322.47 ccw(c1088.47,326.84) 1094.65,326.84 ccw(c1100.82,326.84) OTG.B6@1096.45,322.47 ; OTG.B6@1094.65,298.22 1094.65,363.53 D8.2@1109.92,378.81 1086.58,402.15 1086.58,484.2 R10.1@1104.88,502.5 ; 1094.65,334.94 cw(c1107.74,334.94) v1@1098.48,344.19 ; 1094.65,361.24 ccw(c1107.74,361.24) v1@1098.48,351.99 ; R10.1@1096.41,502.5 cw(c1075.98,502.5) 1090.43,488.05 cw(c1104.88,473.6) R10.1@1104.88,494.03 ; D8.2@1109.92,370.34 ccw(c1109.92,349.91) 1095.47,364.36 ccw(c1081.02,378.81) 1101.46,378.81 ccw(c1081.02,378.81) 1095.47,393.26 ccw(c1109.92,407.71) D8.2@1109.92,387.27
  Bottom Layer w6.69: v1(1054.58,348.09) v1(1094.58,348.09) ; v1@1058.48,344.19 cw(c1067.89,334.78) 1067.89,348.09 cw(c1067.89,361.4) v1@1058.48,351.99 ; v1@1090.68,344.19 ccw(c1081.28,334.78) 1081.28,348.09 ccw(c1081.28,361.4) v1@1090.68,351.99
